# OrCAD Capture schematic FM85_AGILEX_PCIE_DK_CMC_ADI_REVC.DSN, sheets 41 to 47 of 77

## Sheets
41 FPGA Gnd 2: size B
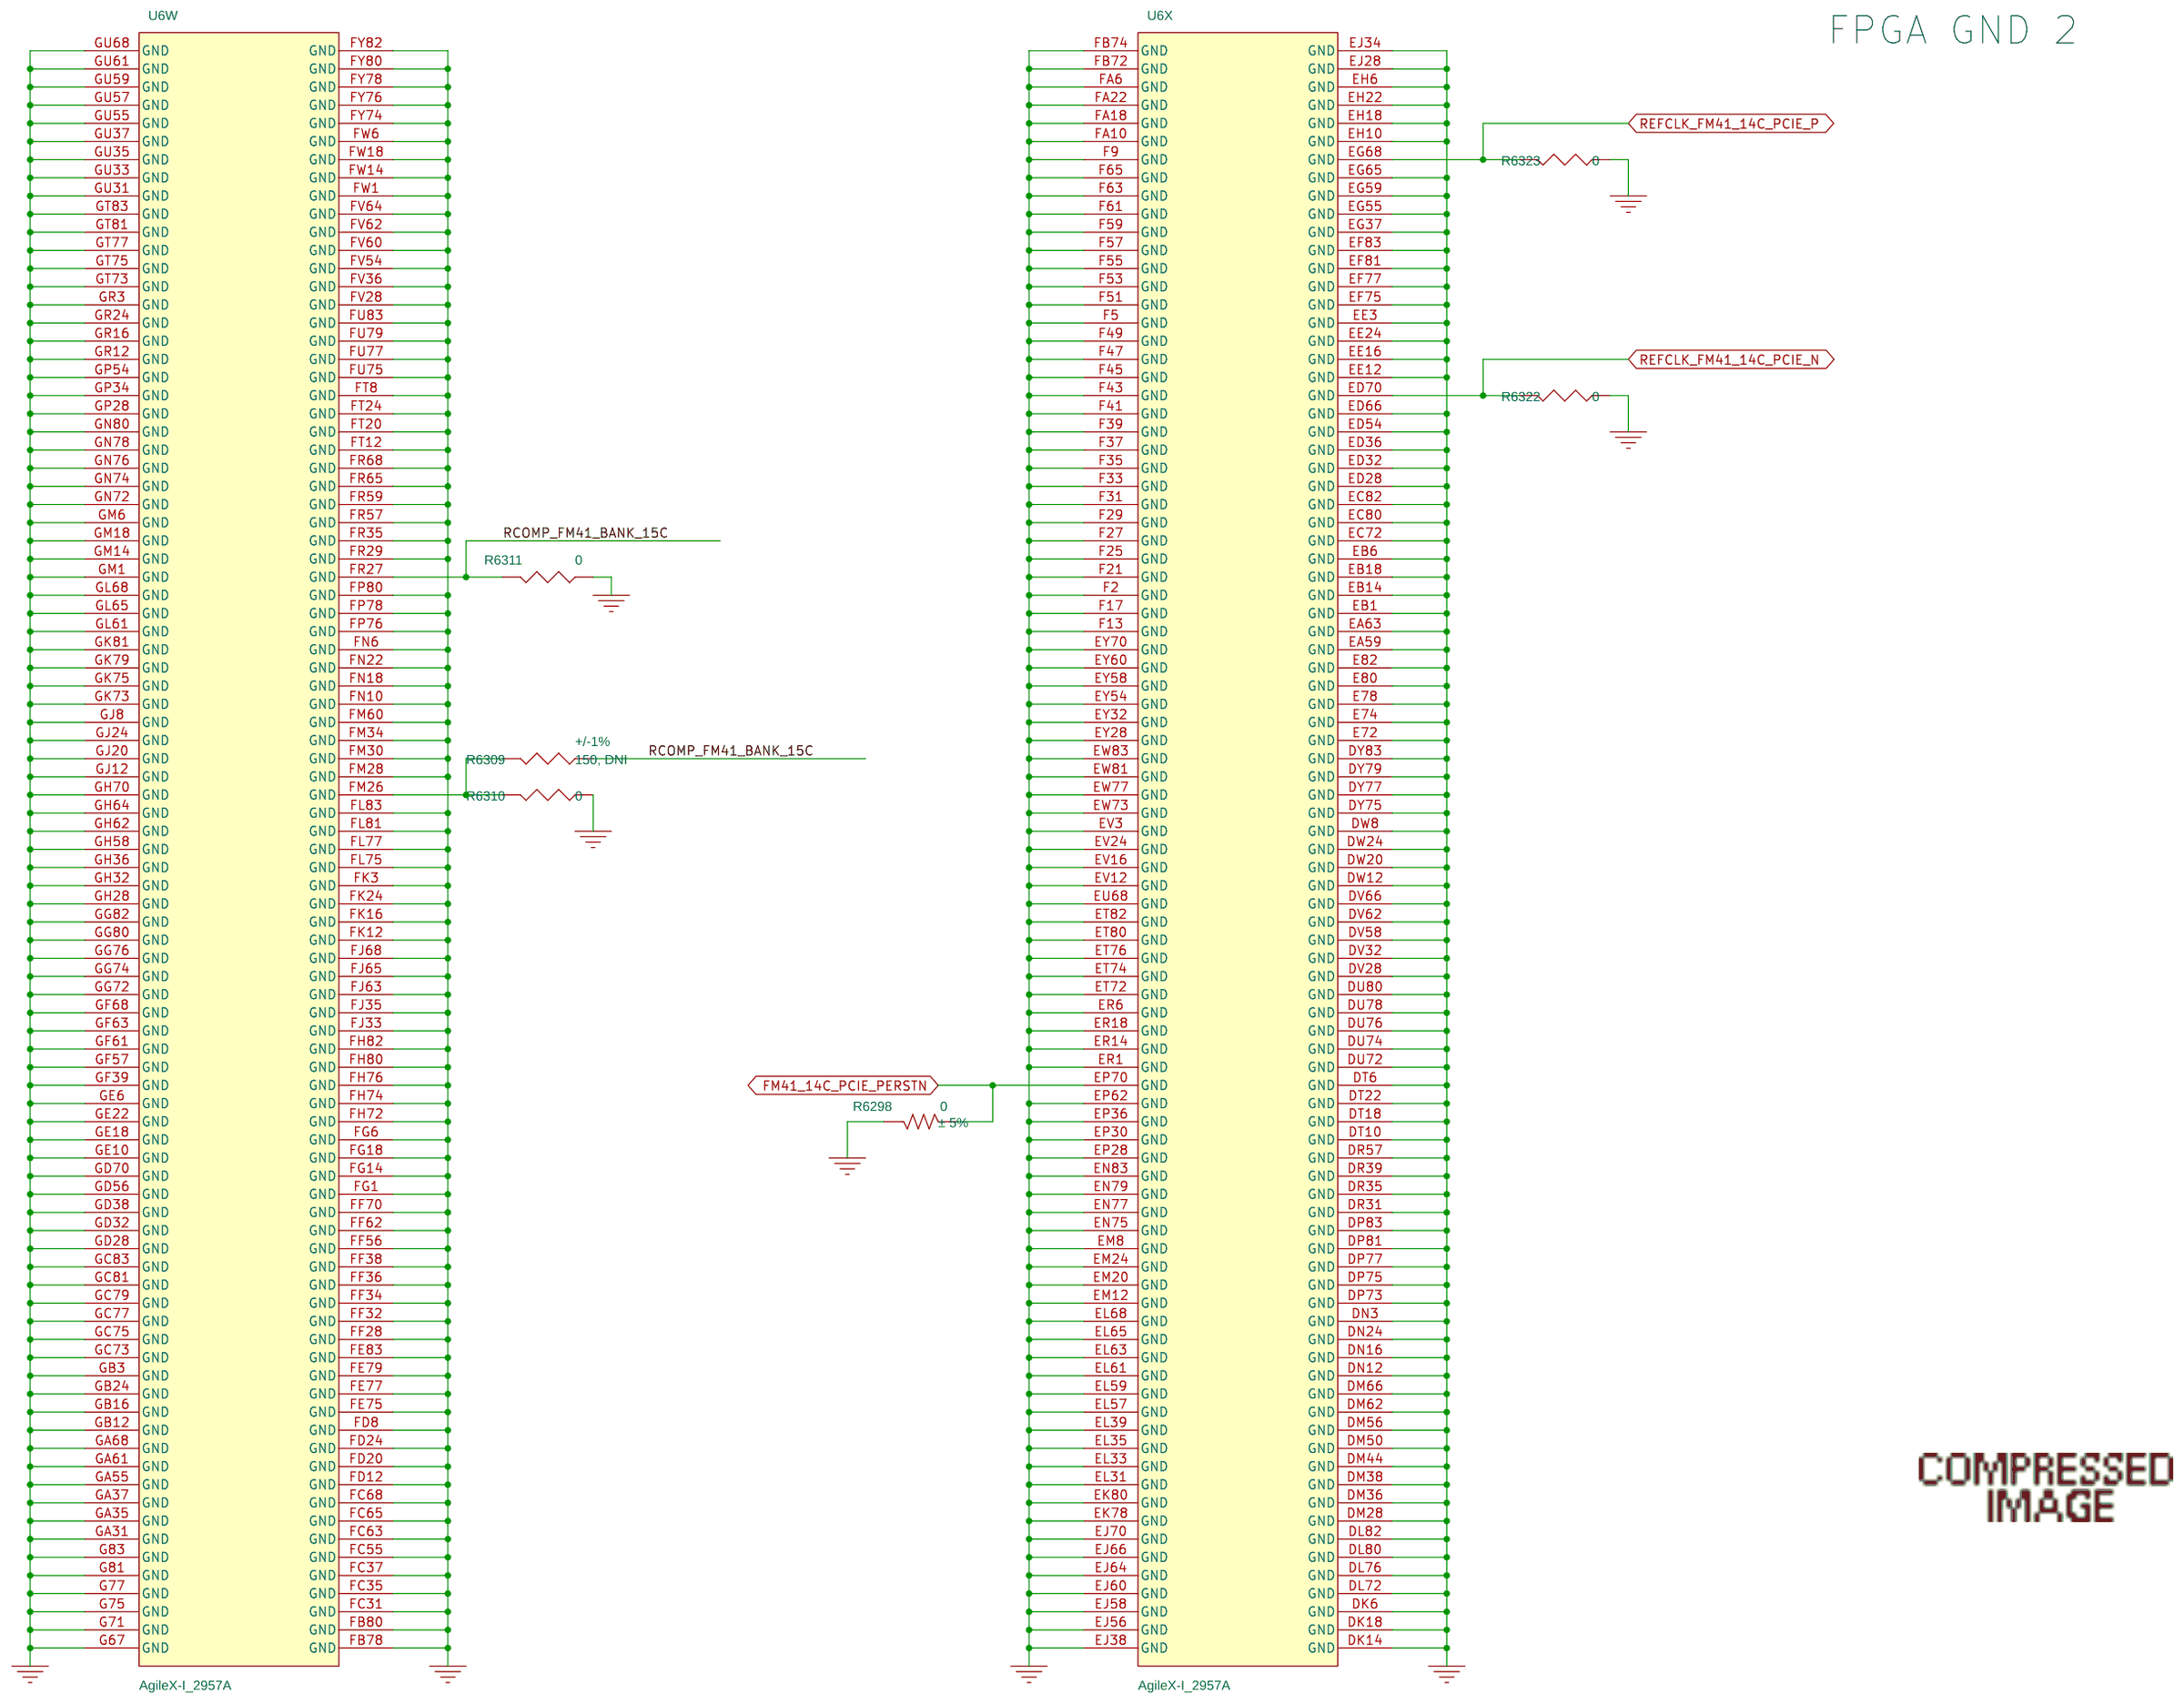
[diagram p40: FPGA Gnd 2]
42 FPGA Gnd 3: size B
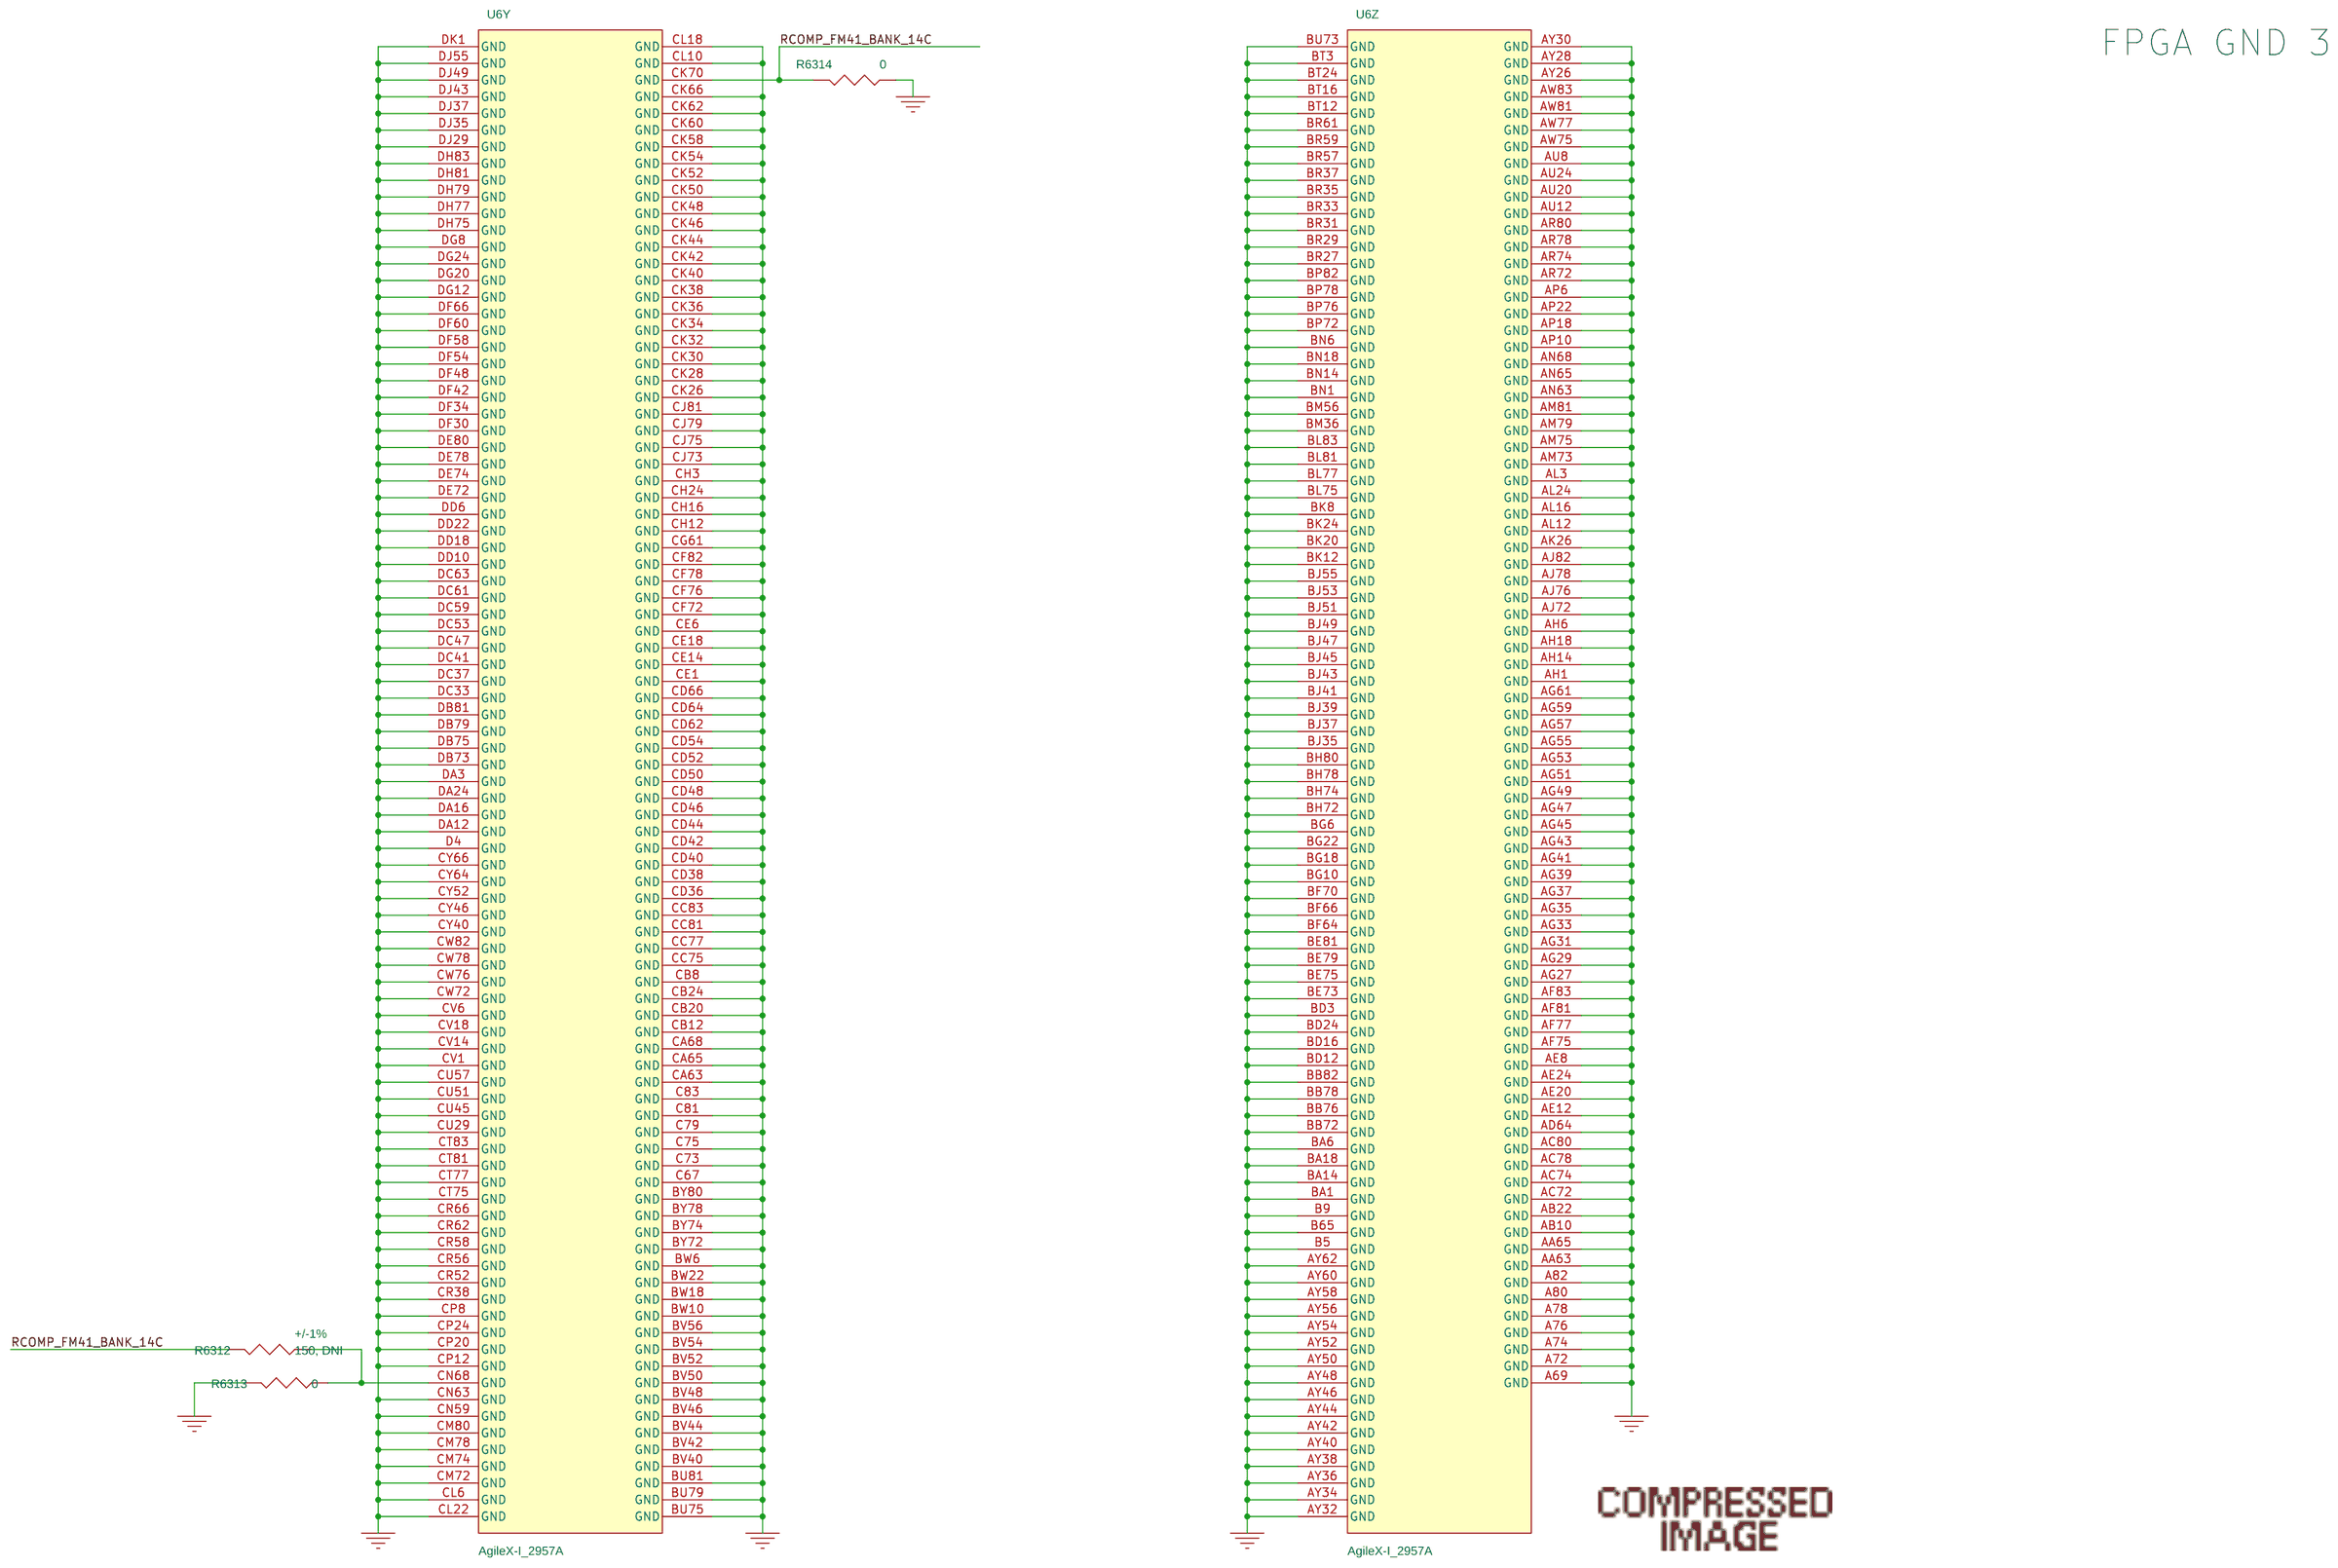
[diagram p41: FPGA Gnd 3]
43 Clock 1: size B
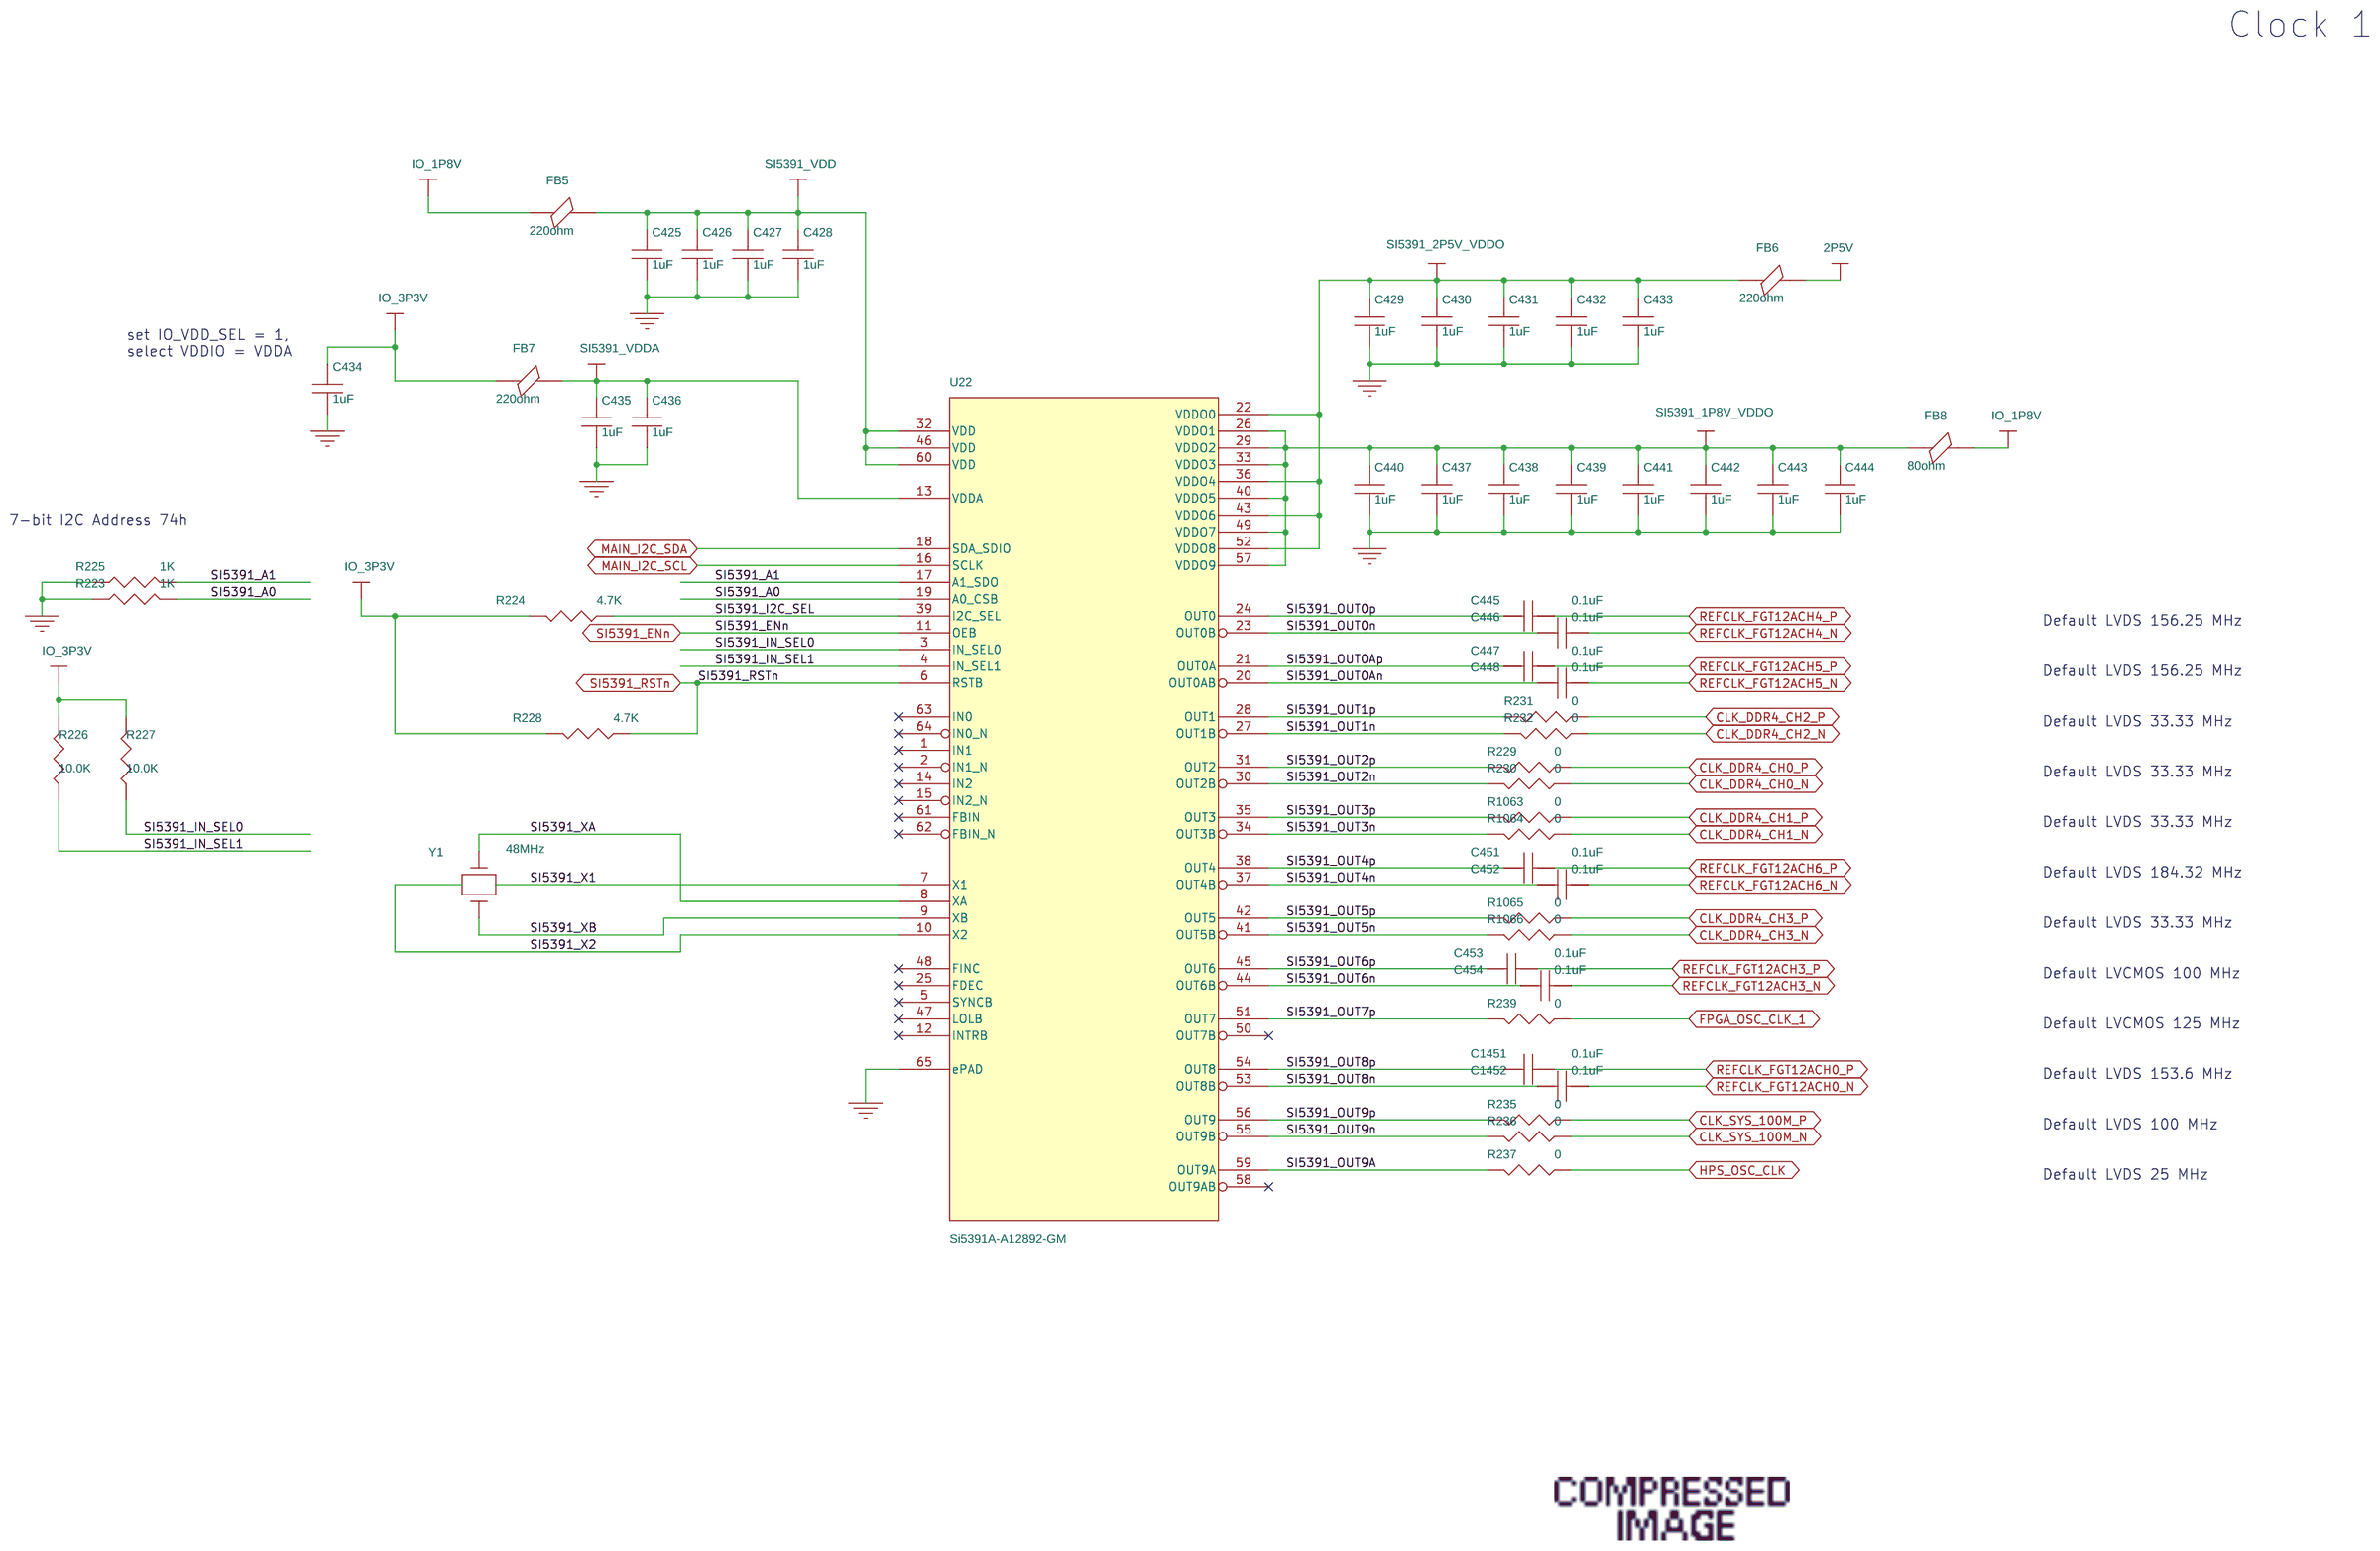
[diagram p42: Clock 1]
44 Clock 2: size B
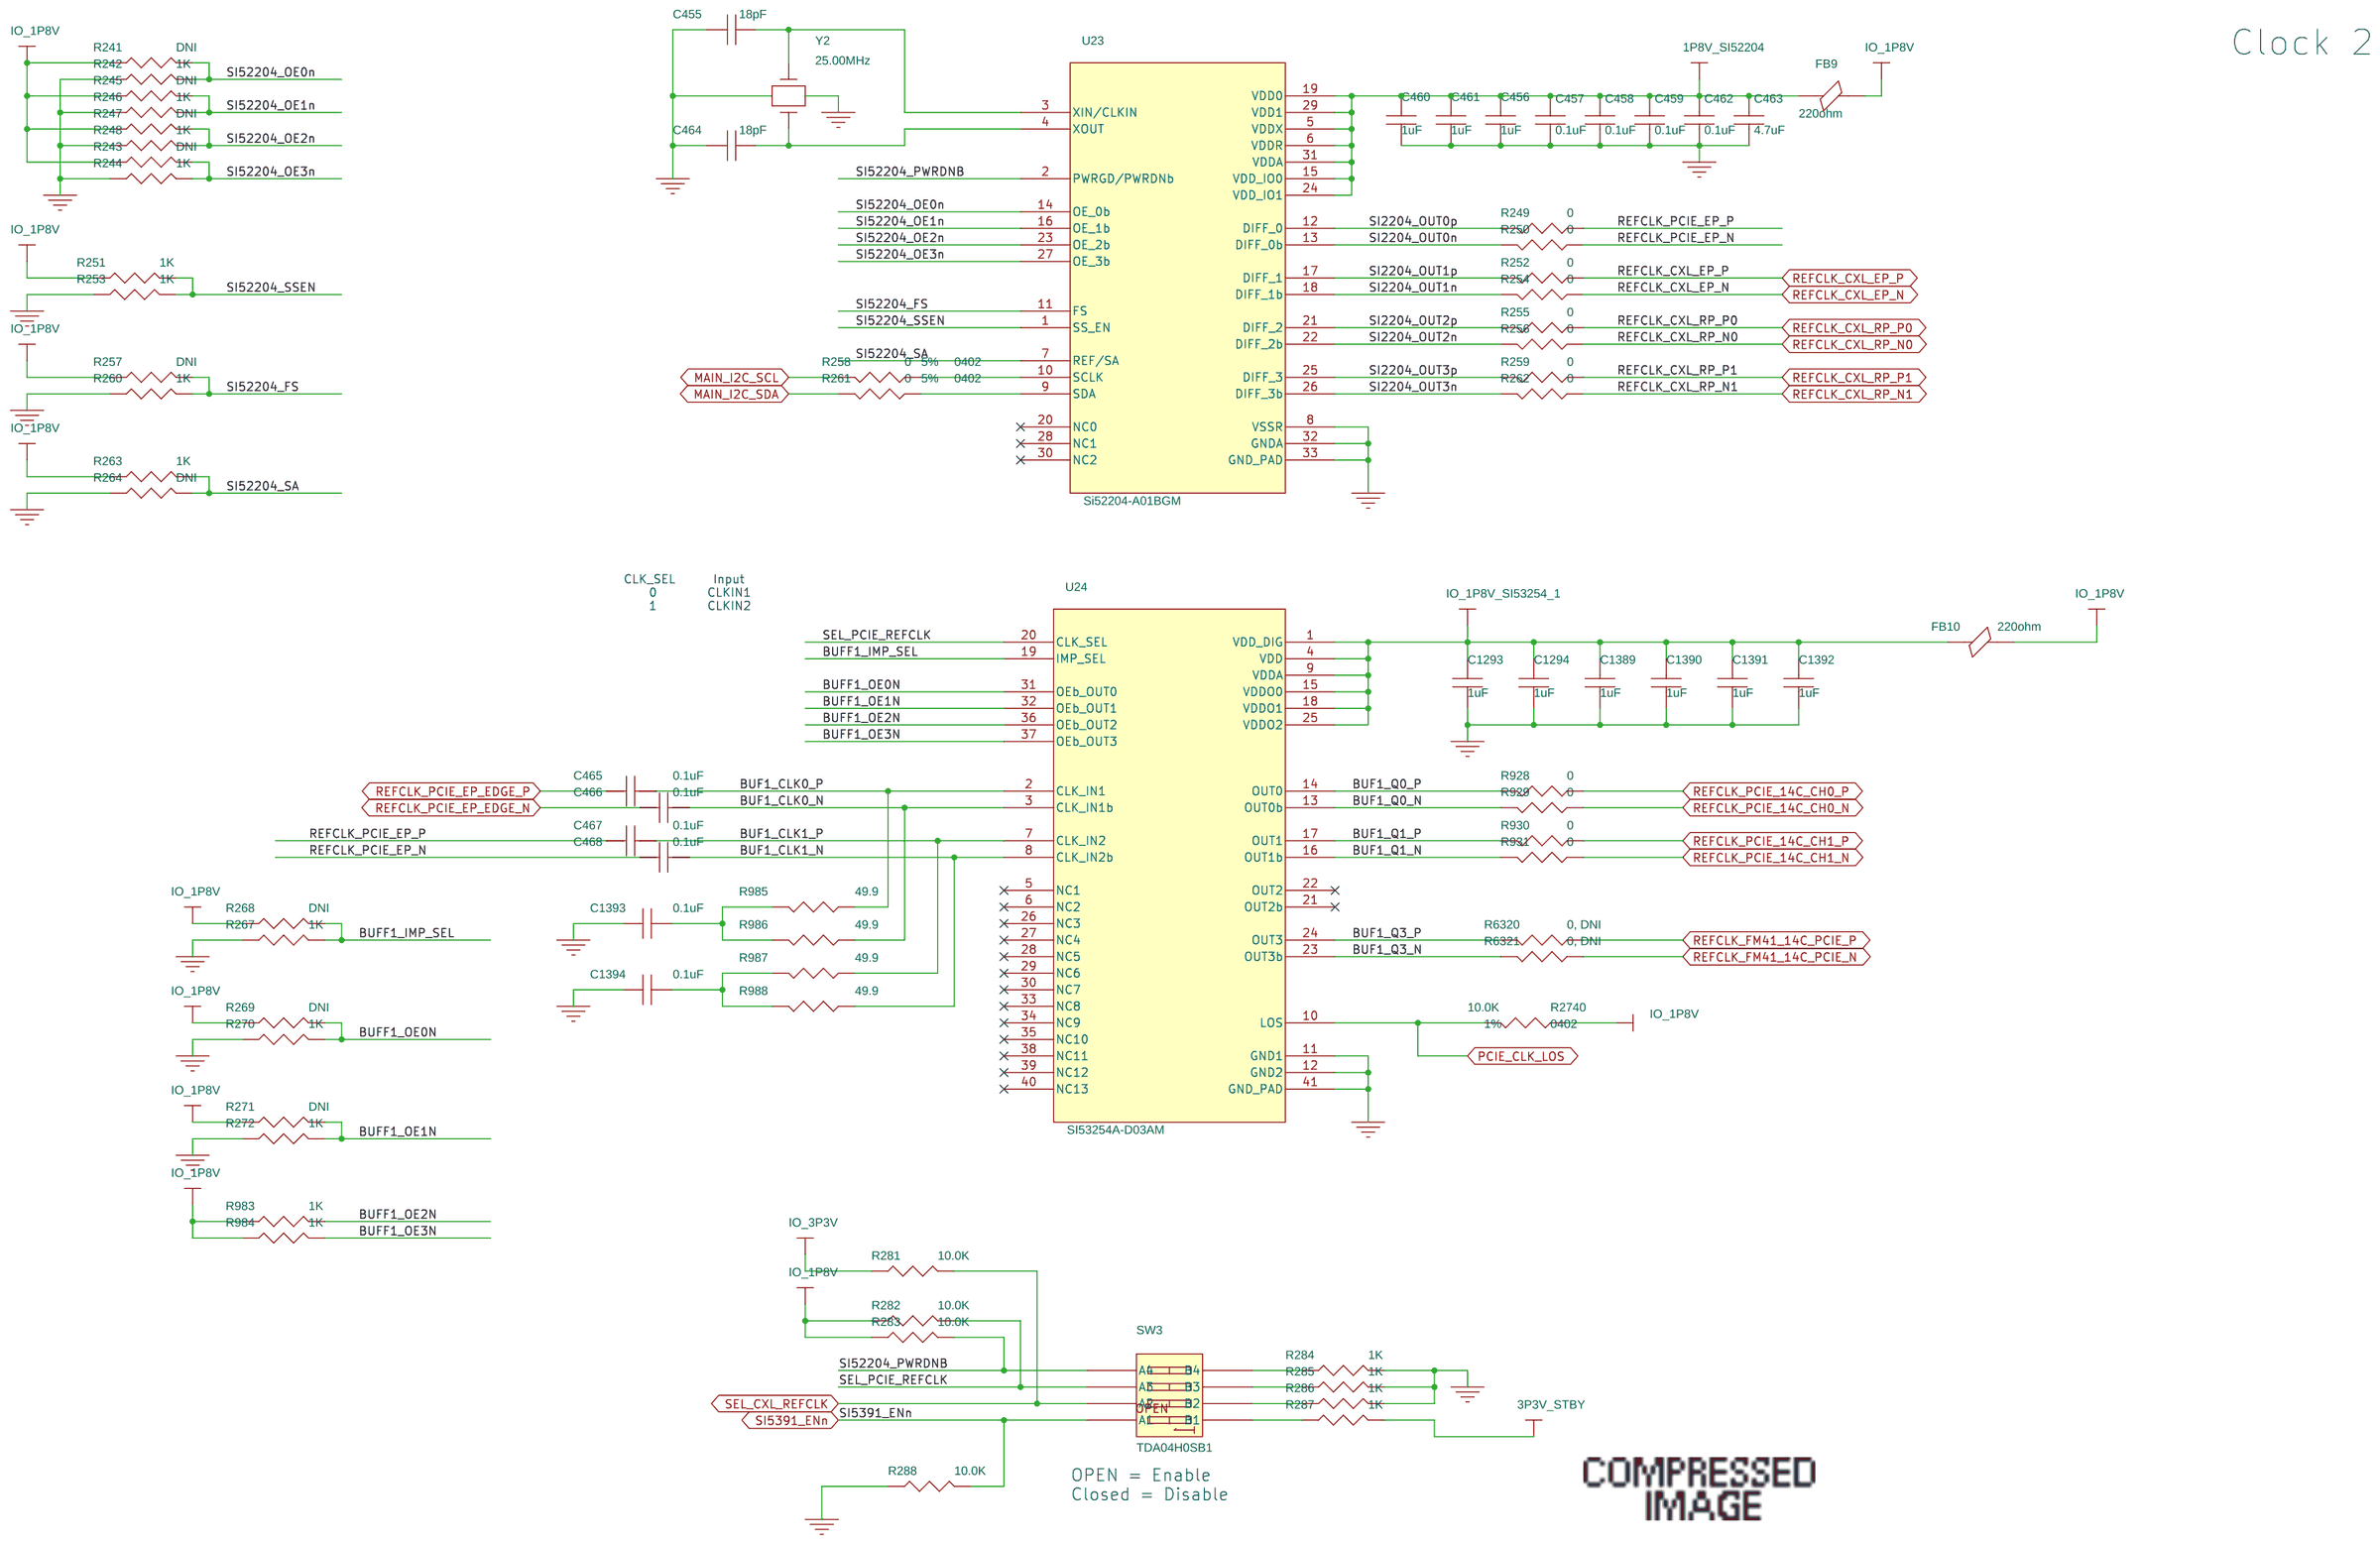
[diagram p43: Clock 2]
45 Clock 3: size B
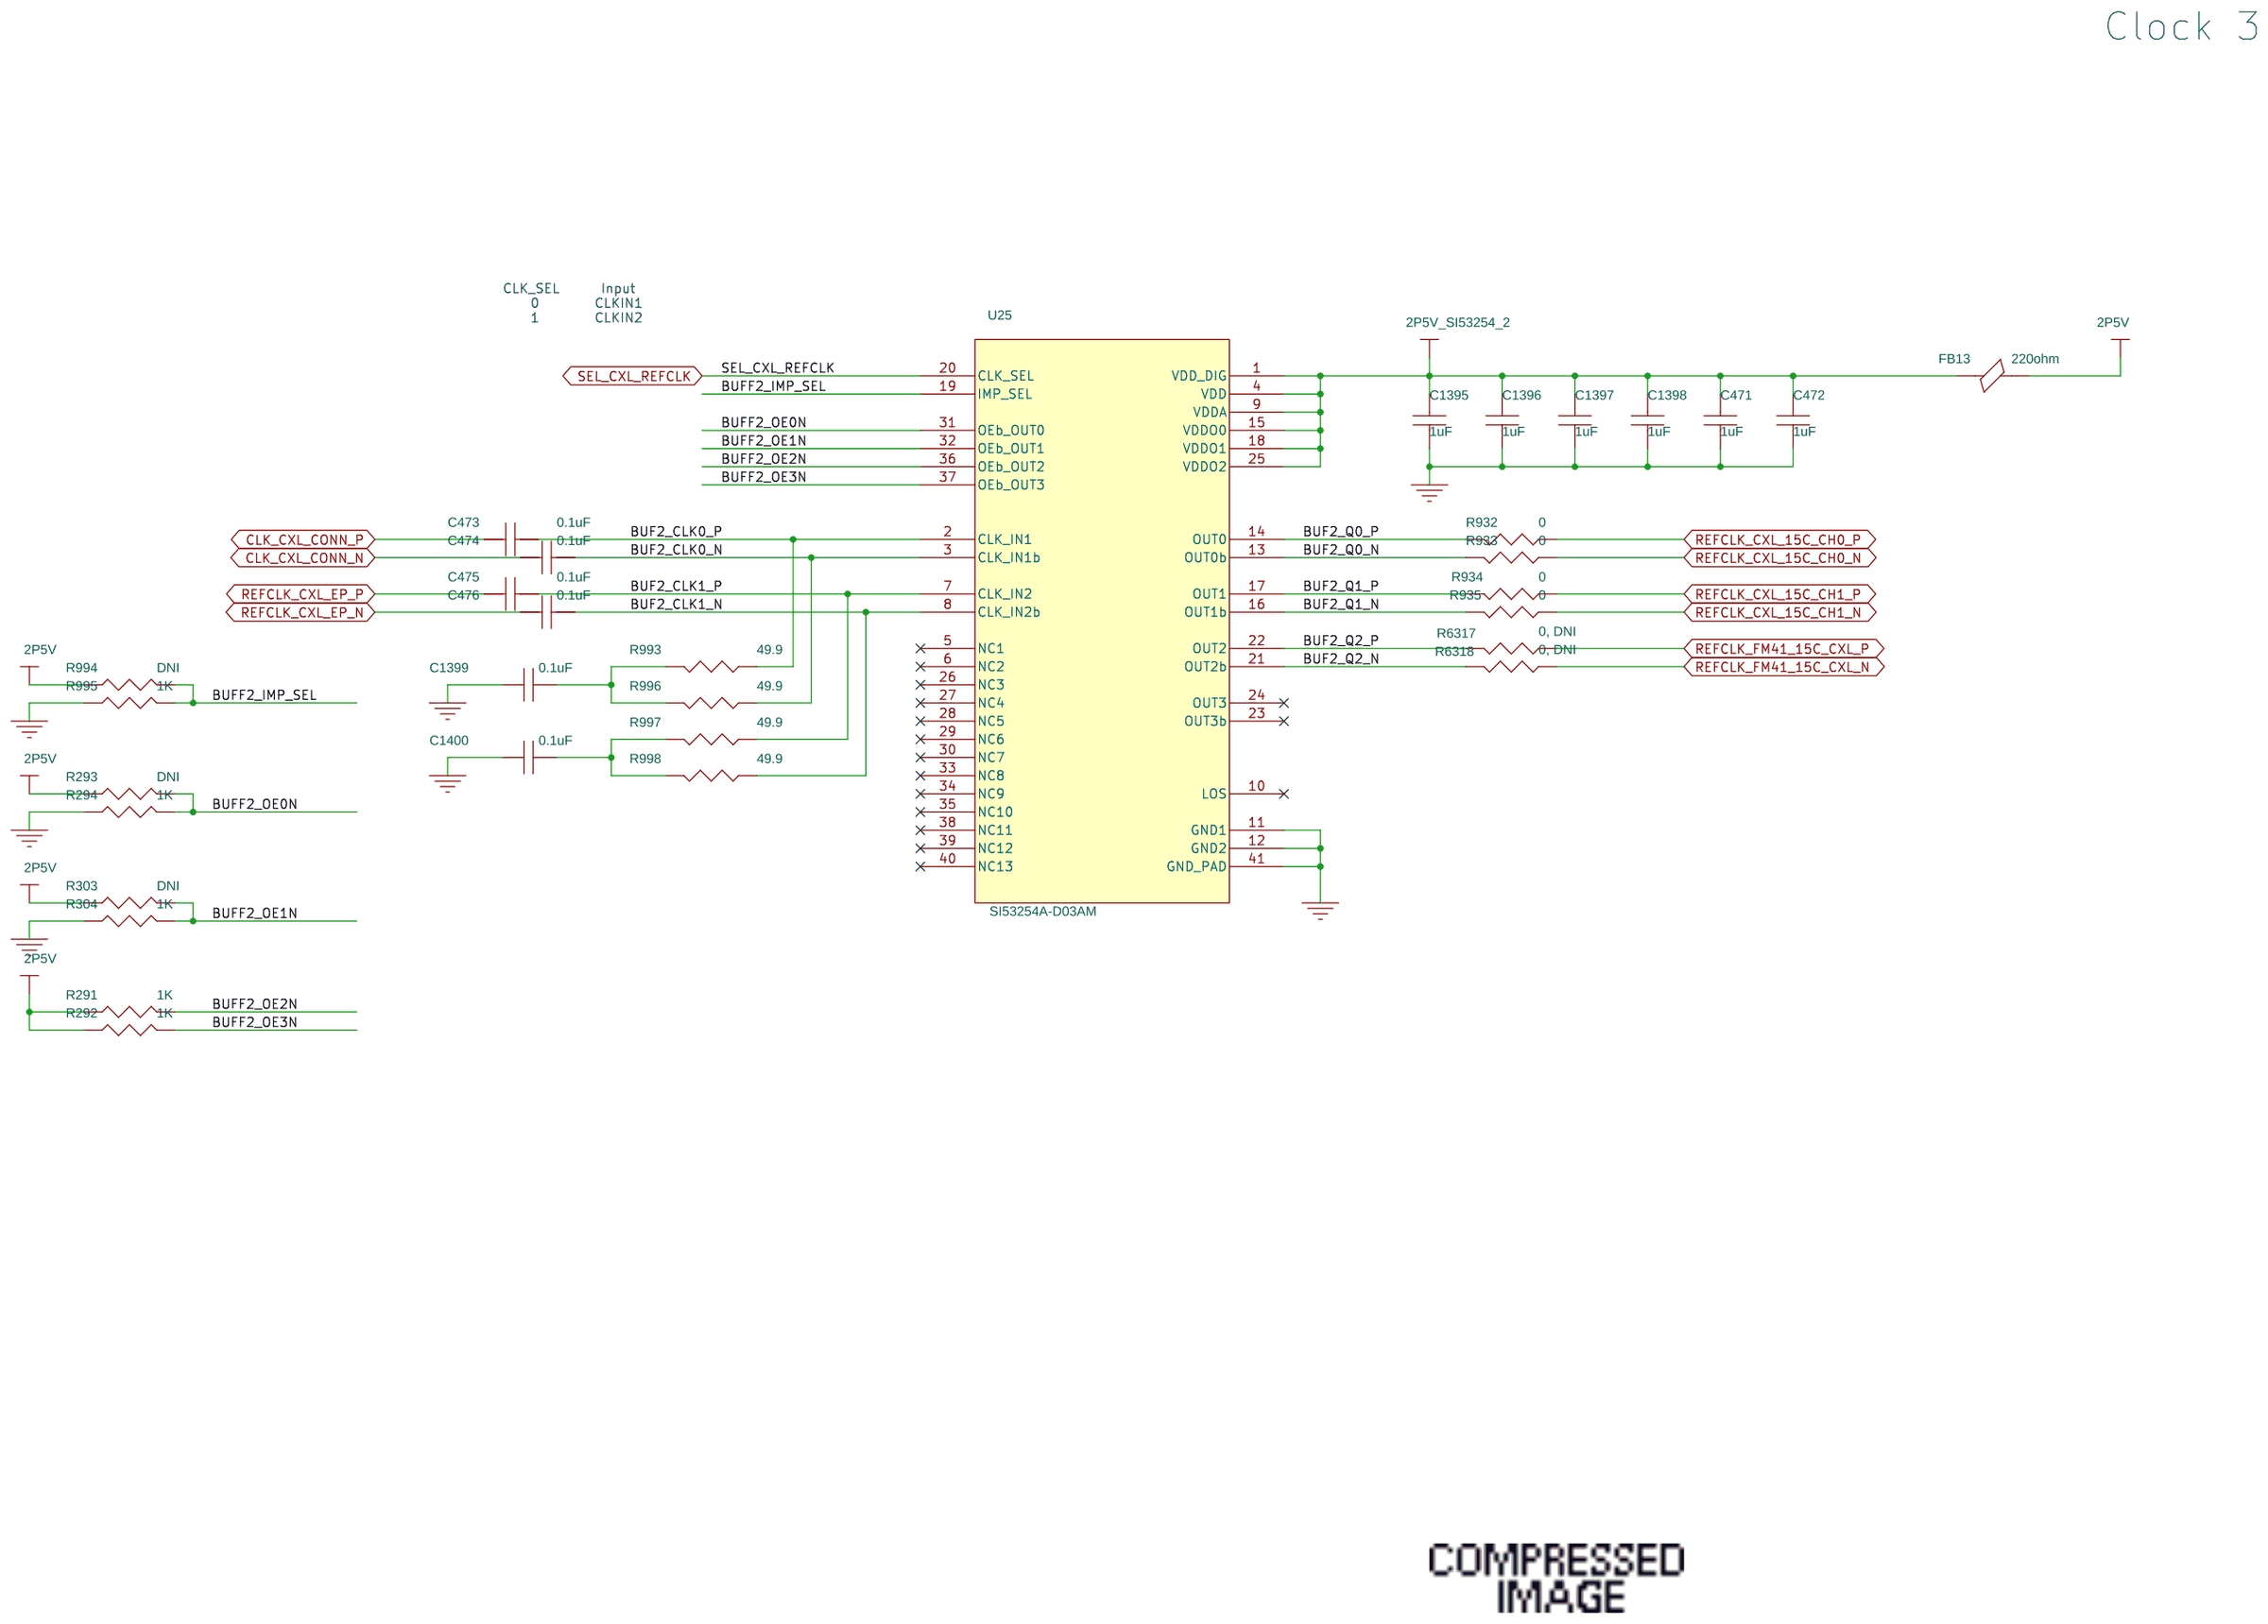
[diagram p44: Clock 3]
46 I2C And PMBUS: size B
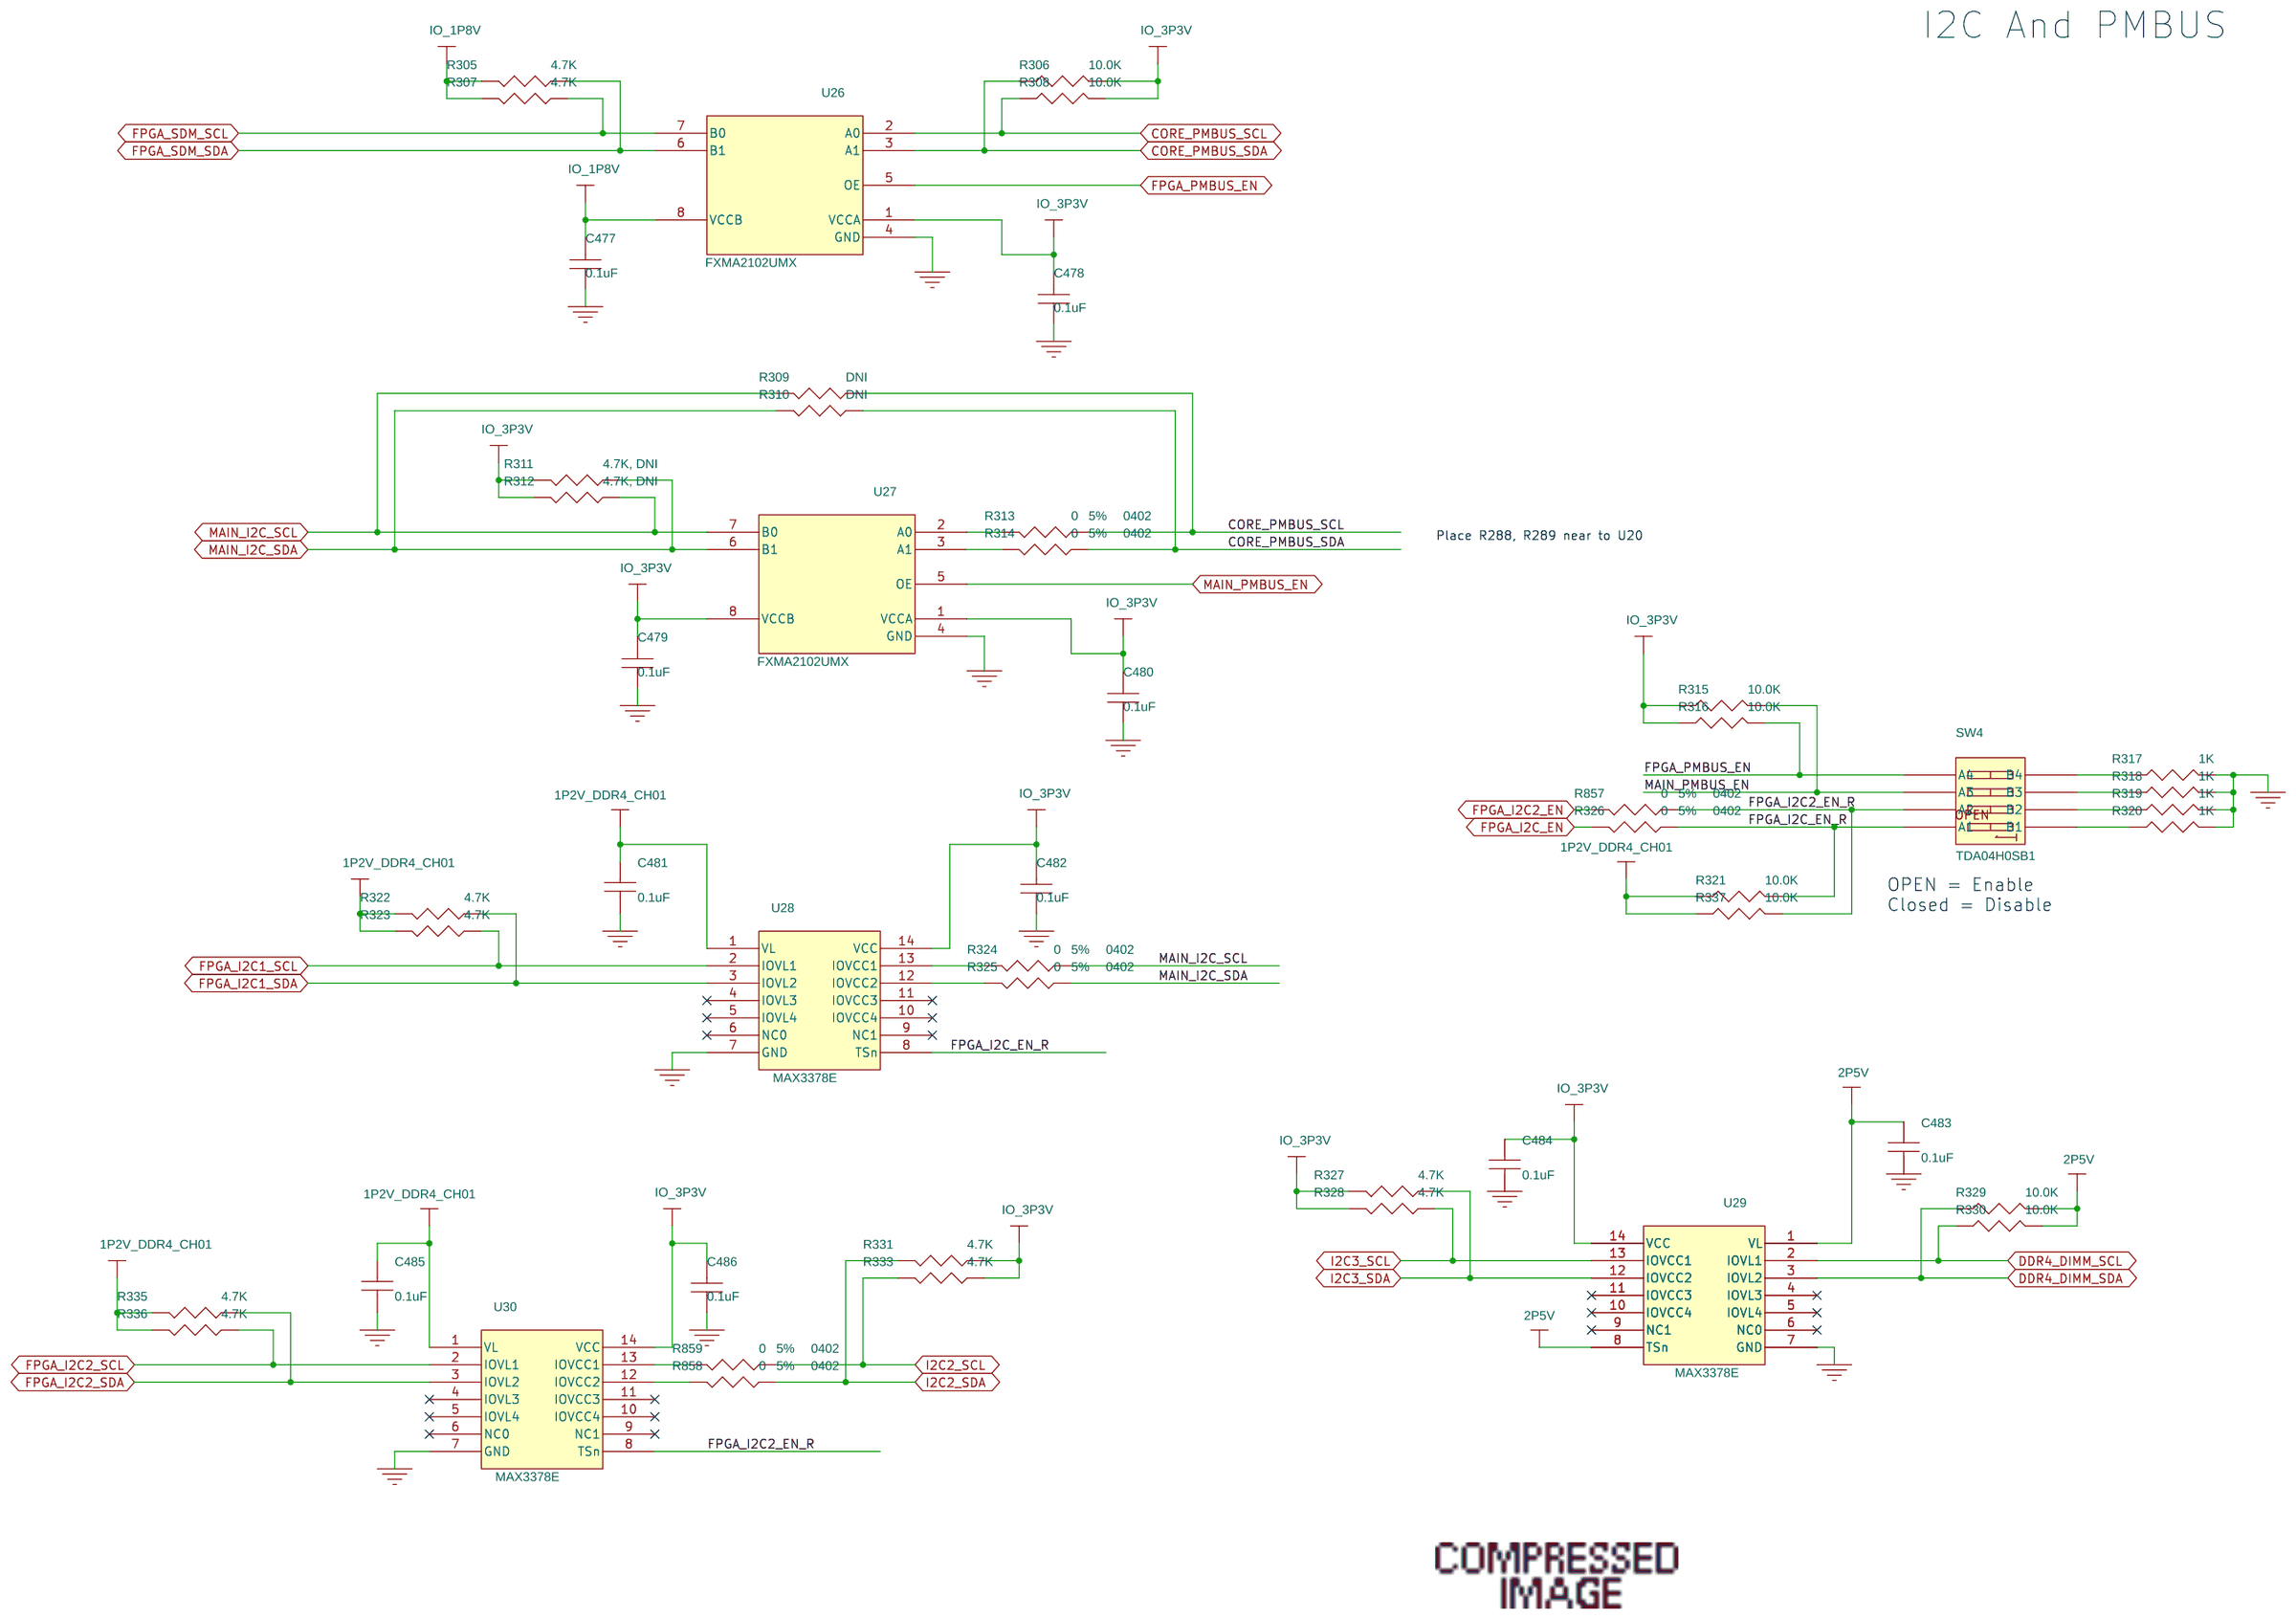
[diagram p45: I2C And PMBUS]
47 LEDs For QSFPDD: size B
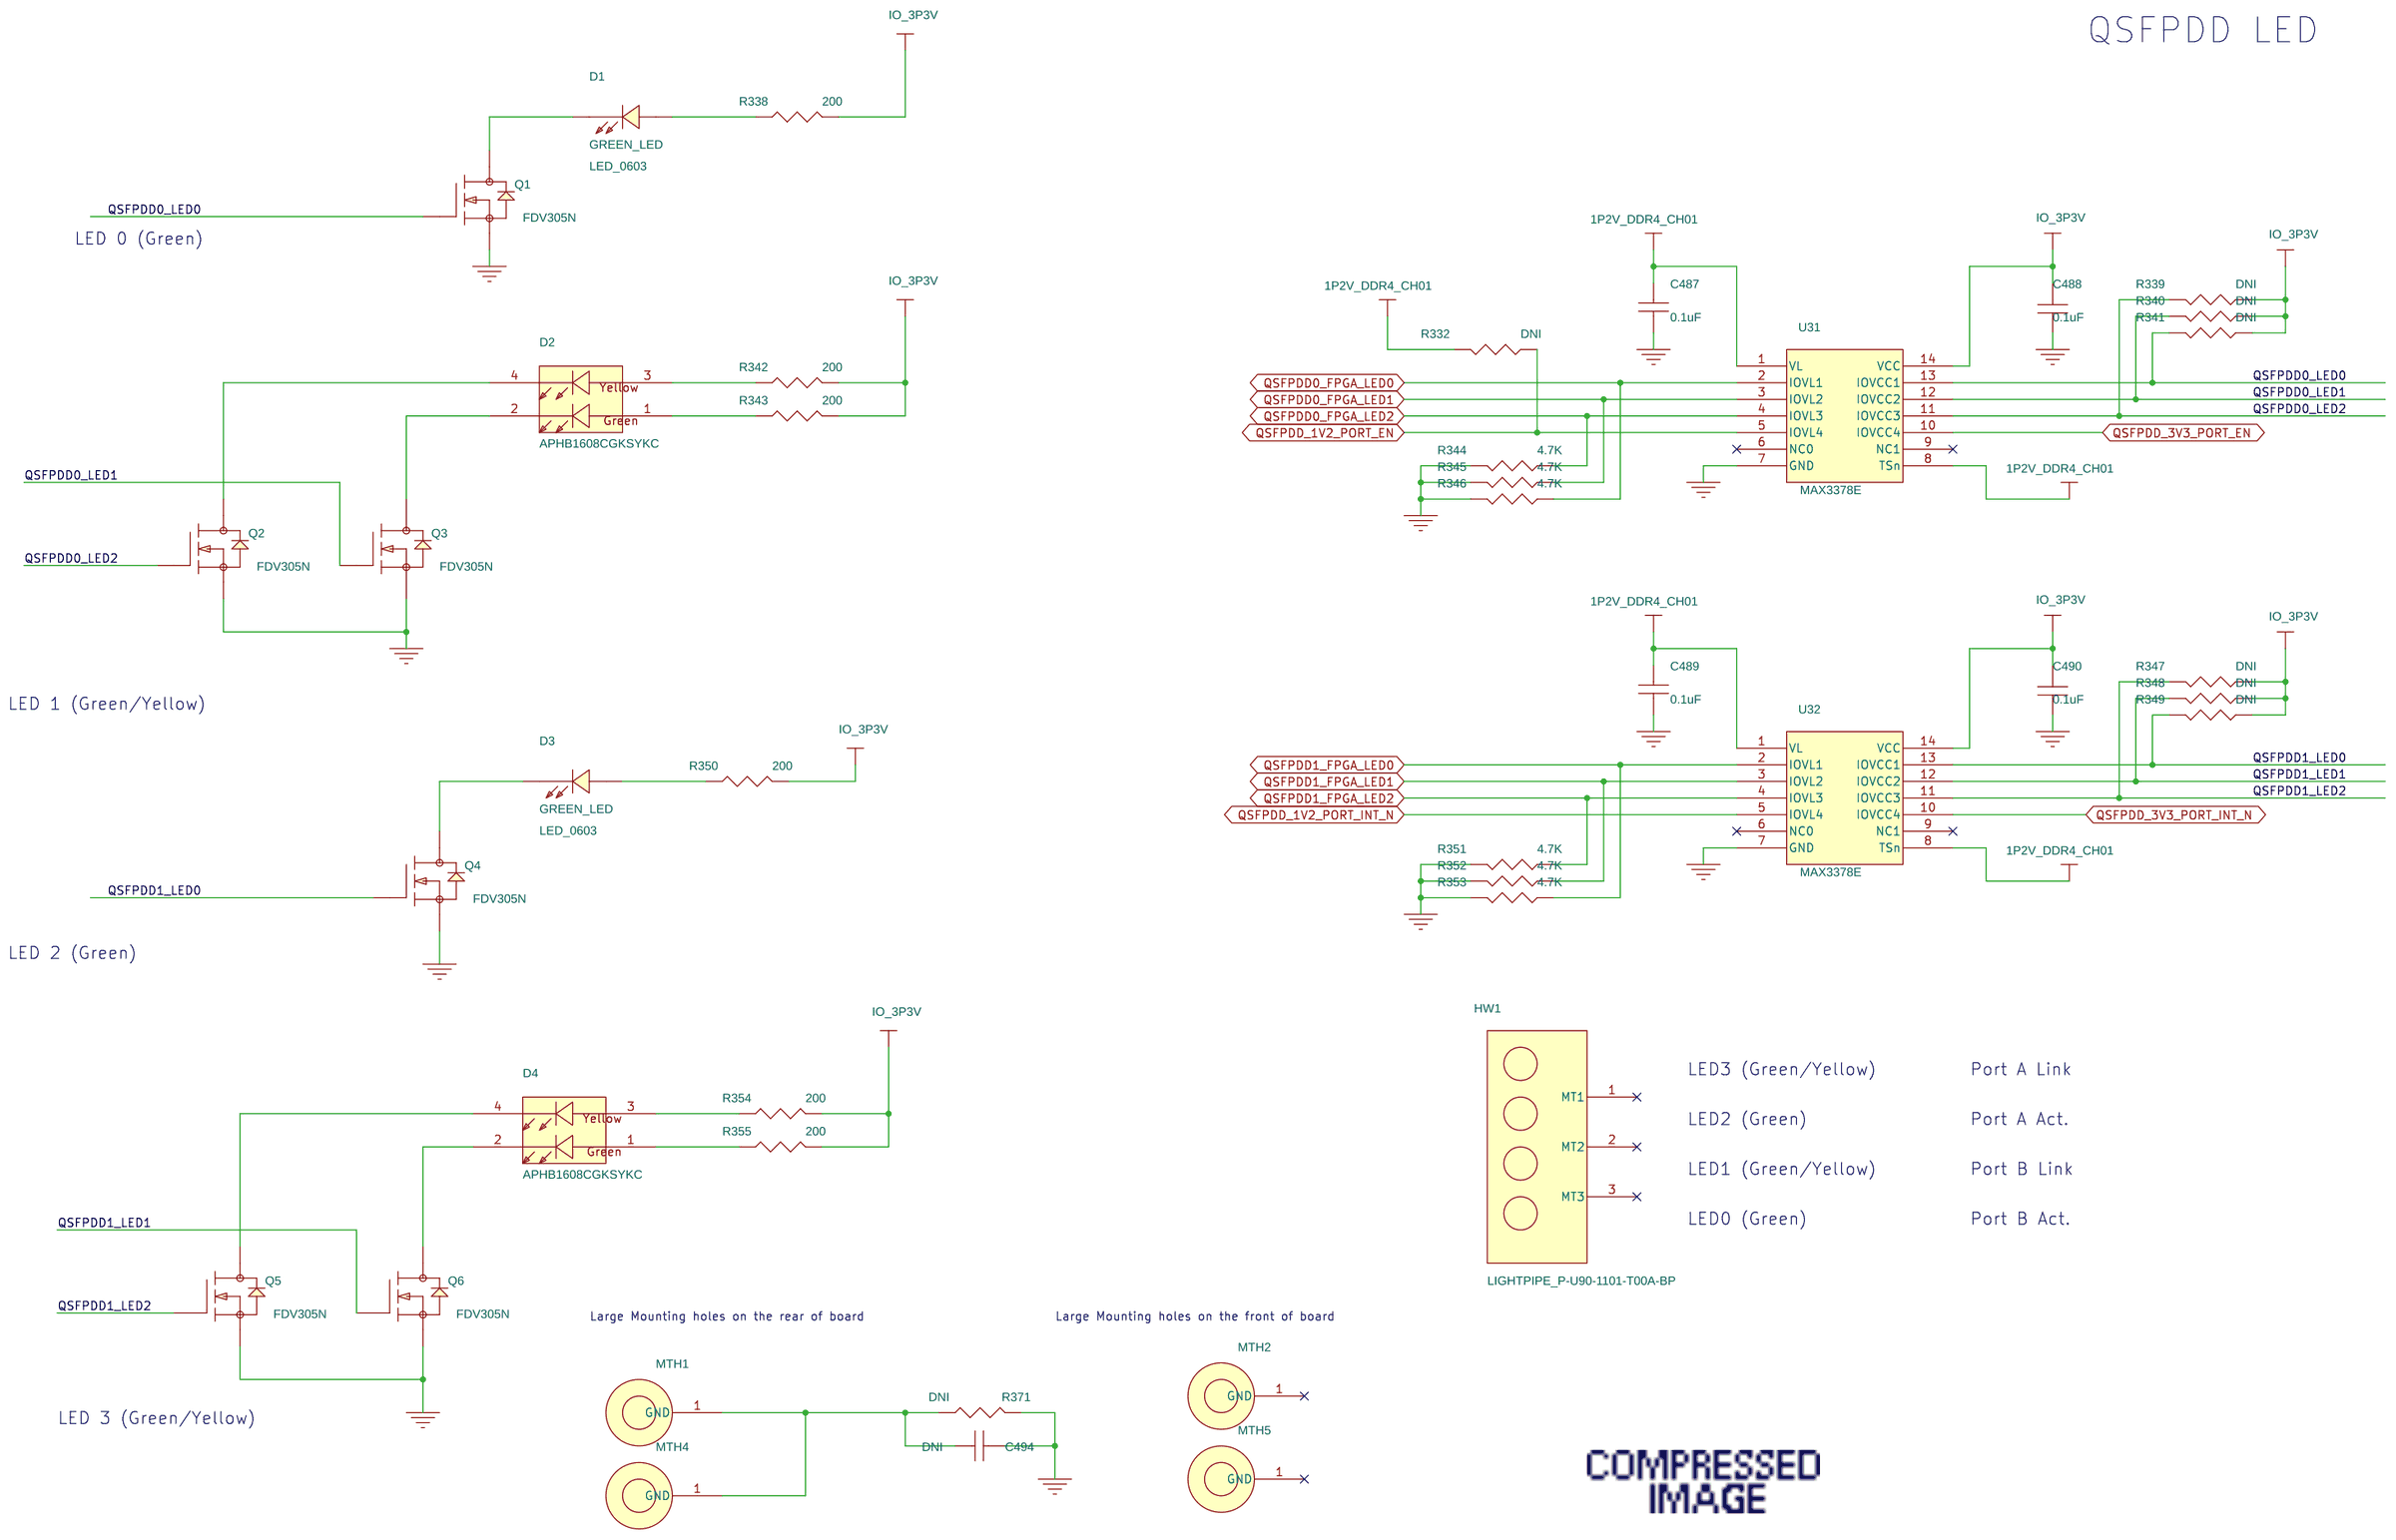
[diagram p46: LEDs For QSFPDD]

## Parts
sheet Clock 1
C425  1uF  [0402]
C426  1uF  [0402]
C427  1uF  [0402]
C428  1uF  [0402]
C429  1uF  [0402]
C430  1uF  [0402]
C431  1uF  [0402]
C432  1uF  [0402]
C433  1uF  [0402]
C434  1uF  [0402]
C435  1uF  [0402]
C436  1uF  [0402]
C437  1uF  [0402]
C438  1uF  [0402]
C439  1uF  [0402]
C440  1uF  [0402]
C441  1uF  [0402]
C442  1uF  [0402]
C443  1uF  [0402]
C444  1uF  [0402]
C445  0.1uF  [0402]
C446  0.1uF  [0402]
C447  0.1uF  [0402]
C448  0.1uF  [0402]
C451  0.1uF  [0402]
C452  0.1uF  [0402]
C453  0.1uF  [0402]
C454  0.1uF  [0402]
C1451  0.1uF  [0402]
C1452  0.1uF  [0402]
FB5  220ohm  [0402]
FB6  220ohm  [0402]
FB7  220ohm  [0402]
FB8  80ohm  [0805]
R223  1K  [0402]
R224  4.7K  [0402]
R225  1K  [0402]
R226  10.0K  [0402]
R227  10.0K  [0402]
R228  4.7K  [0402]
R229  0  [0402]
R230  0  [0402]
R231  0  [0402]
R232  0  [0402]
R235  0  [0402]
R236  0  [0402]
R237  0  [0402]
R239  0  [0402]
R1063  0  [0402]
R1064  0  [0402]
R1065  0  [0402]
R1066  0  [0402]
U22  Si5391A-A12892-GM  [QFN64_9x9_SI5391]
Y1  48MHz  [XTAL_3mmx2mm]
sheet Clock 2
C455  18pF  [0402]
C456  1uF  [0402]
C457  0.1uF  [0402]
C458  0.1uF  [0402]
C459  0.1uF  [0402]
C460  1uF  [0402]
C461  1uF  [0402]
C462  0.1uF  [0402]
C463  4.7uF  [0402]
C464  18pF  [0402]
C465  0.1uF  [0402]
C466  0.1uF  [0402]
C467  0.1uF  [0402]
C468  0.1uF  [0402]
C1293  1uF  [0402]
C1294  1uF  [0402]
C1389  1uF  [0402]
C1390  1uF  [0402]
C1391  1uF  [0402]
C1392  1uF  [0402]
C1393  0.1uF  [0402]
C1394  0.1uF  [0402]
FB9  220ohm  [0402]
FB10  220ohm  [0402]
R241  DNI  [0402]
R242  1K  [0402]
R243  DNI  [0402]
R244  1K  [0402]
R245  DNI  [0402]
R246  1K  [0402]
R247  DNI  [0402]
R248  1K  [0402]
R249  0  [0402]
R250  0  [0402]
R251  1K  [0402]
R252  0  [0402]
R253  1K  [0402]
R254  0  [0402]
R255  0  [0402]
R256  0  [0402]
R257  DNI  [0402]
R258  0  [0402]
R259  0  [0402]
R260  1K  [0402]
R261  0  [0402]
R262  0  [0402]
R263  1K  [0402]
R264  DNI  [0402]
R267  1K  [0402]
R268  DNI  [0402]
R269  DNI  [0402]
R270  1K  [0402]
R271  DNI  [0402]
R272  1K  [0402]
R281  10.0K  [0402]
R282  10.0K  [0402]
R283  10.0K  [0402]
R284  1K  [0402]
R285  1K  [0402]
R286  1K  [0402]
R287  1K  [0402]
R288  10.0K  [0402]
R928  0  [0402]
R929  0  [0402]
R930  0  [0402]
R931  0  [0402]
R983  1K  [0402]
R984  1K  [0402]
R985  49.9  [0402]
R986  49.9  [0402]
R987  49.9  [0402]
R988  49.9  [0402]
R2740  10.0K  [0402]
R6320  0, DNI  [0402]
R6321  0, DNI  [0402]
SW3  TDA04H0SB1  [DIPSWITCH_SMT_QUAD]
U23  Si52204-A01BGM  [QFN32L]
U24  SI53254A-D03AM  [SI53254_QFN40]
Y2  25.00MHz  [XTAL_FA-128]
sheet Clock 3
C471  1uF  [0402]
C472  1uF  [0402]
C473  0.1uF  [0402]
C474  0.1uF  [0402]
C475  0.1uF  [0402]
C476  0.1uF  [0402]
C1395  1uF  [0402]
C1396  1uF  [0402]
C1397  1uF  [0402]
C1398  1uF  [0402]
C1399  0.1uF  [0402]
C1400  0.1uF  [0402]
FB13  220ohm  [0402]
R291  1K  [0402]
R292  1K  [0402]
R293  DNI  [0402]
R294  1K  [0402]
R303  DNI  [0402]
R304  1K  [0402]
R932  0  [0402]
R933  0  [0402]
R934  0  [0402]
R935  0  [0402]
R993  49.9  [0402]
R994  DNI  [0402]
R995  1K  [0402]
R996  49.9  [0402]
R997  49.9  [0402]
R998  49.9  [0402]
R6317  0, DNI  [0402]
R6318  0, DNI  [0402]
U25  SI53254A-D03AM  [SI53254_QFN40]
sheet FPGA BANK 2F
U6  AgileX-I_2957A  [fbga2957a_hex_p56x45]  (sections A,B,C,D,E,F,G,H,I,J,K,L,M,N,O,P,Q,R,S,T,U,V,W,X,Y,Z)
sheet FPGA Gnd 2
R6298  0  [RESC1005X40L20L]
R6309  150, DNI  [0402]
R6310  0  [0402]
R6311  0  [0402]
R6322  0  [0402]
R6323  0  [0402]
sheet FPGA Gnd 3
R6312  150, DNI  [0402]
R6313  0  [0402]
R6314  0  [0402]
sheet I2C And PMBUS
C477  0.1uF  [0402]
C478  0.1uF  [0402]
C479  0.1uF  [0402]
C480  0.1uF  [0402]
C481  0.1uF  [0402]
C482  0.1uF  [0402]
C483  0.1uF  [0402]
C484  0.1uF  [0402]
C485  0.1uF  [0402]
C486  0.1uF  [0402]
R305  4.7K  [0402]
R306  10.0K  [0402]
R307  4.7K  [0402]
R308  10.0K  [0402]
R309  DNI  [0402]
R310  DNI  [0402]
R311  4.7K, DNI  [0402]
R312  4.7K, DNI  [0402]
R313  0  [0402]
R314  0  [0402]
R315  10.0K  [0402]
R316  10.0K  [0402]
R317  1K  [0402]
R318  1K  [0402]
R319  1K  [0402]
R320  1K  [0402]
R321  10.0K  [0402]
R322  4.7K  [0402]
R323  4.7K  [0402]
R324  0  [0402]
R325  0  [0402]
R326  0  [0402]
R327  4.7K  [0402]
R328  4.7K  [0402]
R329  10.0K  [0402]
R330  10.0K  [0402]
R331  4.7K  [0402]
R333  4.7K  [0402]
R335  4.7K  [0402]
R336  4.7K  [0402]
R337  10.0K  [0402]
R857  0  [0402]
R858  0  [0402]
R859  0  [0402]
SW4  TDA04H0SB1  [DIPSWITCH_SMT_QUAD]
U26  FXMA2102UMX  [UMLP]
U27  FXMA2102UMX  [UMLP]
U28  MAX3378E  [TSSOP-14]
U29  MAX3378E  [TSSOP-14]
U30  MAX3378E  [TSSOP-14]
sheet LEDs For QSFPDD
C487  0.1uF  [0402]
C488  0.1uF  [0402]
C489  0.1uF  [0402]
C490  0.1uF  [0402]
C494  DNI  [1206]
D1  GREEN_LED  [LED_0603]
D2  APHB1608CGKSYKC  [LED0603_4Pin_APHB1608]
D3  GREEN_LED  [LED_0603]
D4  APHB1608CGKSYKC  [LED0603_4Pin_APHB1608]
HW1  LIGHTPIPE_P-U90-1101-T00A-BP  [LIGHTPIPE_P-U90-1101-T00A-BP]
MTH1  MT_HOLE_GND  [MH_D125C175T_TB315]
MTH2  MT_HOLE_GND  [MH_D125C175T_TB315]
MTH4  MT_HOLE_GND  [MH_D125C175T_TB315]
MTH5  MT_HOLE_GND  [MH_D125C175T_TB315]
Q1  FDV305N  [SOT23]
Q2  FDV305N  [SOT23]
Q3  FDV305N  [SOT23]
Q4  FDV305N  [SOT23]
Q5  FDV305N  [SOT23]
Q6  FDV305N  [SOT23]
R332  DNI  [0402]
R338  200  [0402]
R339  DNI  [0402]
R340  DNI  [0402]
R341  DNI  [0402]
R342  200  [0402]
R343  200  [0402]
R344  4.7K  [0402]
R345  4.7K  [0402]
R346  4.7K  [0402]
R347  DNI  [0402]
R348  DNI  [0402]
R349  DNI  [0402]
R350  200  [0402]
R351  4.7K  [0402]
R352  4.7K  [0402]
R353  4.7K  [0402]
R354  200  [0402]
R355  200  [0402]
R371  DNI  [0402]
U31  MAX3378E  [TSSOP-14]
U32  MAX3378E  [TSSOP-14]

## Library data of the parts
C425-C444 = CAP: CAP - CER, 1uF, 10V, +/-10%, X5R, 0402; Item Num: G61001-001; Lead Free Status: Yes; Manufacturer: Murata; Manufacturer Part Num: GRM155R61A105KE15D; Num Pins: 2; Part Class: CAPACITORS; RoHS Compliant: Yes
C445-C448 C451-C454 C465-C468 C473-C476 C1393 C1394 C1399 C1400 C1451 C1452 = CAP: CAPC,  X7R, 0402, 0.1uF, 25V, ±20%; Dielectric: X5R; Item Num: K13660-001; LIFECYCLE_PHASE: Active; Lead Free Status: Lead Free; Manufacturer: Murata; Manufacturer Part Num: GRM155R71E104KE14D; Num Pins: 2; Part Class: CAPACITORS; Price: 0.07; RoHS Compliant: RoHS Compliant; Tolerance: +80%/-20%
FB5-FB7 = BEAD_FERRITE_SM: FER-BEAD,0402,220.0OHM,580.0MA,+/-25%; Imax (A): 600mA; Item Num: A51464-023; Manufacturer: Murata Electronics; Manufacturer Part Num: BLM15AX221SN1D; Rdc (Ohms): 350mOhm; Tolerance (%): 25%
FB8 = BEAD_FERRITE_SM: FERRITE,CHIP,POWER,80OHM,SMD; Imax (A): 300mA; Item Num: G32678-001; Manufacturer: Laird-Signal Integrity Products; Manufacturer Part Num: HI0805R800R-10; Rdc (Ohms): 350mOhm; Tolerance (%): 25%
R223 R225 R241-R248 R251 R253 R257 R260 R263 R264 R267-R272 R284-R287 R291-R294 R303 R304 R317-R320 R983 R984 R994 R995 = RESISTOR: RES,1.00K OHMS,1.0%,1/16W,0402; Item Num: G60609-021; Lead Free Status: No; Manufacturer: Panasonic; Manufacturer Part Num: ERJ-2RKF1001X; Num Pins: 2; Part Class: Resistors
R224 R228 R305 R307 R311 R312 R322 R323 R327 R328 R331-R333 R335 R336 R339-R341 R344-R349 R351-R353 = RESISTOR: RES 4.7K OHM 1/16W 5% 0402 SMD; Item Num: A93549-020; Lead Free Status: No; Manufacturer: Panasonic; Manufacturer Part Num: ERJ-2GEJ472X; Manufacturer's Part No.: ERJ-2GEJ472X; Num Pins: 2; Part Class: RESISTORS; Price: 0; RoHS Compliant: Yes
R226 R227 R281-R283 R288 R306 R308 R315 R316 R321 R329 R330 R337 = RESISTOR: RES,10.0K OHMS,1.0%,1/16W, 0402; AGILE_LINK: http://sj-agile9app/Agile/PLMServlet?action=OpenEmailObject&classid=10000&objid=146548997; Item Num: K28115-001; LIFECYCLE_PHASE: Active; Lead Free Status: No; MFR_LIFECYCLE: Active; Manufacturer: Panasonic; Manufacturer Part Num: ERJ-2RKF1002X; Num Pins: 2; PART_SUBCLASS: RESISTORS; POWER: 1/16W; RoHS Compliant: Yes; TOLERANCE: +/-1%
R229-R232 R235-R237 R239 R249 R250 R252 R254-R256 R259 R262 R928-R935 R1063-R1066 = RES_0_OHM_5%_1_16W_0402_SMD: Item Num: H30887-001
U22 = Si5341A-A-GM_0: SILABS 5391A CLK CHIP FM85,FPGA DK U22 (PRE-PROG)ADDR 74H; Item Num: M27305-001; Manufacturer: Silicon Laboratories; Manufacturer Part Num: SI5391A-A12892-GM
Y1 = CRYSTAL_SM_13: CRYSTAL - 48MHz +/-10ppm 8pF 23OHM -40°C ~ 85°C AEC-Q200 4-SMD DFN; Item Num: K15539-001; Lead Free Status: Yes; MFR_LIFECYCLE: Active; Manufacturer: AVX Corp/Kyocera Corp; Manufacturer Part Num: CX3225SB48000D0FPJC1; Num Pins: 4; RoHS Compliant: Yes
C455 C464 = CAP: CAP - CERAMIC, 18PF, 5%, 50V, 0402, COG; AGILE_LINK: http://sj-agile9app/Agile/PLMServlet?action=OpenEmailObject&classid=10000&objid=213459014; Item Num: E60713-001; Lead Free Status: Lead Free; MFR_LIFECYCLE: Active; Manufacturer: Murata; Manufacturer Part Num: GRM1555C1H180JZ01D; Num Pins: 2; PART_SUBCLASS: CAPACITORS; RoHS Compliant: Yes
C456 C460 C461 C471 C472 C1293 C1294 C1389-C1392 C1395-C1398 = CAP: CAP - CER, 1uF, 10V, +/-10%, X5R, 0402; Item Num: G61001-001; Lead Free Status: No; Manufacturer: Murata; Manufacturer Part Num: GRM155R61A105KE15D; Num Pins: 2; Part Class: Capacitors; Price: 0; RoHS Compliant: Yes
C457-C459 C462 = CAP: CAPC,  X7R, 0402, 0.1uF, 25V, ±20%; AGILE_LINK: http://sj-agile9app/Agile/PLMServlet?action=OpenEmailObject&classid=10000&objid=213459527; Item Num: K13660-001; LIFECYCLE_PHASE: Active; Lead Free Status: Lead Free; MFR_LIFECYCLE: Active; Manufacturer: Murata; Manufacturer Part Num: GRM155R71E104KE14D; Num Pins: 2; PART_SUBCLASS: CAPACITORS; Part Class: CAPACITORS; RATED_VOLTAGE: 25V; RoHS Compliant: RoHS Compliant; TOLERANCE: +80%/-20%
C463 = CAP: CAP - CER 4.7UF, +/-20%, 6.3V, X5R, 0402; Item Num: A36096-107; Manufacturer: Murata; Manufacturer Part Num: GRM155R60J475ME87D; Tolerance: +/-20%; Voltage: 6.3V
FB9 FB10 FB13 = BEAD_FERRITE_SM: IND - SMD EMI FILTERS/CHIP FERRITE BEAD, 220-OHM @ 100MHZ, 0.35-OHM DCR, 0402; Imax (A): 300mA; Item Num: G79186-002; Manufacturer: Wurth Elektronik; Manufacturer Part Num: 742792780; Rdc (Ohms): 350mOhm; Tolerance (%): 25%
R258 R261 R313 R314 R324-R326 R857-R859 = RESISTOR: RES ZERO OHM 1/16W 5% 0402 SMD; Altera Part No.: P02-14020R; Item Num: H30887-001; Lead Free Status: No; Manufacturer: Panasonic; Manufacturer Part Num: ERJ-2GE0R00X; Num Pins: 2; Part Class: RESISTORS; RoHS Compliant: Yes; Tolerance: 5%
R985-R988 R993 R996-R998 = RESISTOR: RES, 49.9 OHMS, 1%, 1/16W, 0402; Item Num: K16545-001; Lead Free Status: Yes; Manufacturer: NIC Components Corp.; Manufacturer Part Num: NRC04F49R9TRF; Num Pins: 2; Part Class: Resistors; Price: 0
R2740 = RESISTOR: RES,10.0K OHMS,1.0%,1/16W, 0402; AGILE_LINK: http://sj-agile9app/Agile/PLMServlet?action=OpenEmailObject&classid=10000&objid=146548997; Item Num: K28115-001; LIFECYCLE_PHASE: Active; Lead Free Status: No; MFR_LIFECYCLE: Active; Manufacturer: Panasonic; Manufacturer Part Num: ERJ-2RKF1002X; Num Pins: 2; PART_SUBCLASS: RESISTORS; POWER: 1/16W; RESISTANCE: 10K; RoHS Compliant: Yes; TOLERANCE: 1%
R6317 R6318 R6320 R6321 = RESISTOR: RES ZERO OHM 1/16W 5% 0402 SMD; Agile IPN: P02-14020R; Altera Part No.: P02-14020R; Item Num: H30887-001; Lead Free Status: No; Manufacturer: Panasonic; Manufacturer Part Num: ERJ-2GE0R00X; Num Pins: 2; Part Class: RESISTORS; Price: 0; RoHS Compliant: Yes; Tolerance: 5%
SW3 SW4 = SPST4: SWITCHES - 4 POS, 8 PIN, Ultra-mini SMT Half-pitch Slider DIP Switch; AGILE_LINK: http://sj-agile9app/Agile/PLMServlet?action=OpenEmailObject&classid=10000&objid=258073635; Item Num: K15518-001; LIFECYCLE_PHASE: Preliminary; Lead Free Status: Not Lead Free; MFR_LIFECYCLE: Active; Manufacturer: Wurth Electronik; Manufacturer Part Num: 416131160804; Num Pins: 8; PART_SUBCLASS: SWITCHES; RoHS Compliant: RoHS Compliant
U23 = Si52204: IC,CLK_GEN,32,QFN,N/A,GNRTR,PLL,; Item Num: K21260-016; Manufacturer: Silicon Labs Inc.; Manufacturer Part Num: SI52204-A01BGMR
U24 U25 = Si53254A-D02AM: IC,CLK_DRVR,40QFN,N/A,BUF,NON-PLL; Item Num: N45221-001; Manufacturer: Silabs
Y2 = CRYSTAL_SM_13: CRYSTAL - MINI XTL, 25.00MHZ, FREQ +/-50PPM, RANGE +/-30PPM -20~70C, 18PF, 2.0MM X 1.6MM SMD; Item Num: K72195-001; Lead Free Status: Yes; MFR_LIFECYCLE: Active; Manufacturer: Epson Toyocom; Manufacturer Part Num: FA-128 25.0000MB-C; Num Pins: 4; RoHS Compliant: Yes
U6 = AgileX-I_2957A: Item Num: 99C7VA
R6298 = Resistor,_0402_0: RES D,0402,0.00 OHM,5.00%,1/16W; Agile Part Number: 02495; Item Num: A93549-001; Manufacturer: YAGEO CORP.; Manufacturer Part Num: ERJ-2GE0R00X; Package: 0402; Part Number: ERJ-2GE0R00X; Tolerance: ± 5%
R6309 R6312 = RESISTOR: RES,150 OHMS,1.0%,1/16W,0402; Item Num: G60609-012; Manufacturer: Yageo; Manufacturer Part Num: RC0402FR-07150RL; Num Pins: 2; Part Class: RESISTORS; TOLERANCE: +/-1%
R6310 R6311 R6313 R6314 R6322 R6323 = RESISTOR: RES ZERO OHM 1/16W 5% 0402 SMD; Agile IPN: P02-14020R; Altera Part No.: P02-14020R; Item Num: H30887-001; Lead Free Status: No; Manufacturer: Panasonic; Manufacturer Part Num: ERJ-2GE0R00X; Num Pins: 2; Part Class: RESISTORS; RoHS Compliant: Yes; Tolerance: 5%
C477-C480 C482 C486 C488 C490 = CAP: CAPC,  X7R, 0402, 0.1uF, 25V, ±20%; Item Num: K13660-001; LIFECYCLE_PHASE: Active; Lead Free Status: Lead Free; Manufacturer: Murata; Manufacturer Part Num: GRM155R71E104KE14D; Num Pins: 2; Part Class: CAPACITORS; Price: 0; RoHS Compliant: RoHS Compliant
C481 C484 C485 C489 = CAP: CAPC,  X7R, 0402, 0.1uF, 25V, ±20%; Dielectric: Y5V; Item Num: K13660-001; LIFECYCLE_PHASE: Active; Lead Free Status: Lead Free; MFR_LIFECYCLE: Active; Manufacturer: Murata; Manufacturer Part Num: GRM155R71E104KE14D; Num Pins: 2; PART_SUBCLASS: CAPACITORS; Part Class: CAPACITORS; RATED_VOLTAGE: 25V; RoHS Compliant: RoHS Compliant; Tolerance: +80%/-20%
C483 C487 = CAP: CAPC,  X7R, 0402, 0.1uF, 25V, ±20%; Dielectric: X7R; Item Num: K13660-001; LIFECYCLE_PHASE: Active; Lead Free Status: Lead Free; MFR_LIFECYCLE: Active; Manufacturer: Murata; Manufacturer Part Num: GRM155R71E104KE14D; Num Pins: 2; PART_SUBCLASS: CAPACITORS; Part Class: CAPACITORS; RATED_VOLTAGE: 25V; RoHS Compliant: RoHS Compliant; Tolerance: +80%/-20%
R309 R310 = RESISTOR: RES ZERO OHM 1/16W 5% 0402 SMD; Altera Part No.: P02-14020R; Item Num: H30887-001; Lead Free Status: No; Manufacturer: Panasonic; Manufacturer Part Num: ERJ-2GE0R00X; Num Pins: 2; Part Class: RESISTORS; Price: 0; RoHS Compliant: Yes; Tolerance: 5%
U26 U27 = FXMA2102UMX: Dual Supply, 2-Bit Voltage Translator/Buffer/Repeater/Isolator for I2C application; Item Num: E87189-001; Manufacturer: Fairchild
U28-U32 = MAX3378E_0: IC - QUAD LOW-VOLTAGE LEVEL TRANSLATOR, +/- 15KV, ESD-PROTECTED, 1UA, 16MBPS; Item Num: C34337-001; Manufacturer: Maxim; Manufacturer Part Num: MAX3378EEUD
C494 = CAP: CAP CER 1000PF 1000V X7R 1206; AGILE_LINK: http://sj-agile9app/Agile/PLMServlet?action=OpenEmailObject&classid=10000&objid=215384813; CAPACITANCE: 1000pF; LIFECYCLE_PHASE: Active; Lead Free Status: Lead Free; MFR_LIFECYCLE: Active; Manufacturer: Murata; Manufacturer Part Num: GRM31BR73A102KW01L; Num Pins: 2; PACKAGING: Tape & Reel (TR); PART_SUBCLASS: CAPACITORS; RATED_VOLTAGE: 1000V; RoHS Compliant: RoHS Compliant; Supplier Part Num: GRM31BR73A102KW01L; Tolerance: +/-10%
D1 D3 = LED_WURTH: LED GREEN CLEAR 0603 SMD; Item Num: J48659-001; Manufacturer: Kingbright; Manufacturer Part Num: APT1608CGCK; Num Pins: 2
D2 D4 = APHB1608CGKSYKC: LED,1608,SM,GRN/YEL,V,1.00,RC,2,; Item Num: G93404-001; Manufacturer: Kingbright
HW1 = LIGHTPIPE_P-U90-1101-T00A-BP_2: QUAD STACKED,LIGHTPIPE - RIGHT ANGLE; IPN: N/A; Item Num: K33020-001; Manufacturer: Amphenol; Manufacturer Part Num: P-U90-1101-T00A-BP
MTH1 MTH2 MTH4 MTH5 = MNT_HOLE_1
Q1-Q6 = PWRMOSFET_EN_GSD_0: IC, MOSFET, N-Channel, 20V; Item Num: K21465-001; Manufacturer: Fairchild; Manufacturer Part Num: FDV305N_NL
R338 R342 R343 R350 R354 R355 = RESISTOR: RES 200 OHM 1/16W 5% 0402 SMD; Item Num: K15618-001; Manufacturer: Panasonic; Manufacturer Part Num: ERJ-2GEJ201X; Num Pins: 2; Part Class: RESISTORS; RoHS Compliant: Yes
R371 = RESISTOR: RES,1M OHMS,5.0%,1/16W,0402; AGILE_LINK: http://sj-agile9app/Agile/PLMServlet?action=OpenEmailObject&classid=10000&objid=146548997; Item Num: K15866-001; LIFECYCLE_PHASE: Active; Lead Free Status: No; MFR_LIFECYCLE: Active; Manufacturer: Panasonic; Manufacturer Part Num: ERJ-2GEJ105X; Num Pins: 2; PART_SUBCLASS: RESISTORS; POWER: 1/16W; RESISTANCE: 1M; RoHS Compliant: Yes; TOLERANCE: +/-5%

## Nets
GND: C425.2 C426.2 C427.2 C428.2 C429.2 C430.2 C431.2 C432.2 C433.2 C434.2 C435.2 C436.2 C437.2 C438.2 C439.2 C440.2 C441.2 C442.2 C443.2 C444.2 C455.2 C456.2 C457.2 C458.2 C459.2 C460.2 C461.2 C462.2 C463.2 C464.2 C471.2 C472.2 C477.1 C478.1 C479.1 C480.1 C481.2 C482.1 C483.2 C484.2 C485.2 C486.1 C487.2 C488.1 C489.2 C490.1 C494.2 C1293.2 C1294.2 C1389.2 C1390.2 C1391.2 C1392.2 C1393.1 C1394.1 C1395.2 C1396.2 C1397.2 C1398.2 C1399.1 C1400.1 Q1.2(SOURCE) Q2.2(SOURCE) Q3.2(SOURCE) Q4.2(SOURCE) Q5.2(SOURCE) Q6.2(SOURCE) R223.2 R225.2 R242.2 R244.2 R246.2 R248.2 R253.2 R260.2 R264.2 R267.2 R270.2 R272.2 R284.1 R285.1 R286.1 R288.1 R294.2 R304.2 R317.1 R318.1 R319.1 R320.1 R344.2 R345.2 R346.2 R351.2 R352.2 R353.2 R371.1 R995.2 R6298.1 R6310.2 R6311.2 R6313.2 R6314.2 R6322.2 R6323.2 U6.A69(GND) U6.A72(GND) U6.A74(GND) U6.A76(GND) U6.A78(GND) U6.A80(GND) U6.A82(GND) U6.AA63(GND) U6.AA65(GND) U6.AB10(GND) U6.AB22(GND) U6.AC72(GND) U6.AC74(GND) U6.AC78(GND) U6.AC80(GND) U6.AD64(GND) U6.AE8(GND) U6.AE12(GND) U6.AE20(GND) U6.AE24(GND) U6.AF75(GND) U6.AF77(GND) U6.AF81(GND) U6.AF83(GND) U6.AG27(GND) U6.AG29(GND) U6.AG31(GND) U6.AG33(GND) U6.AG35(GND) U6.AG37(GND) U6.AG39(GND) U6.AG41(GND) U6.AG43(GND) U6.AG45(GND) U6.AG47(GND) U6.AG49(GND) U6.AG51(GND) U6.AG53(GND) U6.AG55(GND) U6.AG57(GND) U6.AG59(GND) U6.AG61(GND) U6.AH1(GND) U6.AH6(GND) U6.AH14(GND) U6.AH18(GND) U6.AJ72(GND) U6.AJ76(GND) U6.AJ78(GND) U6.AJ82(GND) U6.AK26(GND) U6.AL3(GND) U6.AL12(GND) U6.AL16(GND) U6.AL24(GND) U6.AM73(GND) U6.AM75(GND) U6.AM79(GND) U6.AM81(GND) U6.AN63(GND) U6.AN65(GND) U6.AN68(GND) U6.AP6(GND) U6.AP10(GND) U6.AP18(GND) U6.AP22(GND) U6.AR72(GND) U6.AR74(GND) U6.AR78(GND) U6.AR80(GND) U6.AU8(GND) U6.AU12(GND) U6.AU20(GND) U6.AU24(GND) U6.AW75(GND) U6.AW77(GND) U6.AW81(GND) U6.AW83(GND) U6.AY26(GND) U6.AY28(GND) U6.AY30(GND) U6.AY32(GND) U6.AY34(GND) U6.AY36(GND) U6.AY38(GND) U6.AY40(GND) U6.AY42(GND) U6.AY44(GND) U6.AY46(GND) U6.AY48(GND) U6.AY50(GND) U6.AY52(GND) U6.AY54(GND) U6.AY56(GND) U6.AY58(GND) U6.AY60(GND) U6.AY62(GND) U6.B5(GND) U6.B9(GND) U6.B65(GND) U6.BA1(GND) U6.BA6(GND) U6.BA14(GND) U6.BA18(GND) U6.BB72(GND) U6.BB76(GND) U6.BB78(GND) U6.BB82(GND) U6.BD3(GND) U6.BD12(GND) U6.BD16(GND) U6.BD24(GND) U6.BE73(GND) U6.BE75(GND) U6.BE79(GND) U6.BE81(GND) U6.BF64(GND) U6.BF66(GND) U6.BF70(GND) U6.BG6(GND) U6.BG10(GND) U6.BG18(GND) U6.BG22(GND) U6.BH72(GND) U6.BH74(GND) U6.BH78(GND) U6.BH80(GND) U6.BJ35(GND) U6.BJ37(GND) U6.BJ39(GND) U6.BJ41(GND) U6.BJ43(GND) U6.BJ45(GND) U6.BJ47(GND) U6.BJ49(GND) U6.BJ51(GND) U6.BJ53(GND) U6.BJ55(GND) U6.BK8(GND) U6.BK12(GND) U6.BK20(GND) U6.BK24(GND) U6.BL75(GND) U6.BL77(GND) U6.BL81(GND) U6.BL83(GND) U6.BM36(GND) U6.BM56(GND) U6.BN1(GND) U6.BN6(GND) U6.BN14(GND) U6.BN18(GND) U6.BP72(GND) U6.BP76(GND) U6.BP78(GND) U6.BP82(GND) U6.BR27(GND) U6.BR29(GND) U6.BR31(GND) U6.BR33(GND) U6.BR35(GND) U6.BR37(GND) U6.BR57(GND) U6.BR59(GND) U6.BR61(GND) U6.BT3(GND) U6.BT12(GND) U6.BT16(GND) U6.BT24(GND) U6.BU73(GND) U6.BU75(GND) U6.BU79(GND) U6.BU81(GND) U6.BV40(GND) U6.BV42(GND) U6.BV44(GND) U6.BV46(GND) U6.BV48(GND) U6.BV50(GND) U6.BV52(GND) U6.BV54(GND) U6.BV56(GND) U6.BW6(GND) U6.BW10(GND) U6.BW18(GND) U6.BW22(GND) U6.BY72(GND) U6.BY74(GND) U6.BY78(GND) U6.BY80(GND) U6.C67(GND) U6.C73(GND) U6.C75(GND) U6.C79(GND) U6.C81(GND) U6.C83(GND) U6.CA63(GND) U6.CA65(GND) U6.CA68(GND) U6.CB8(GND) U6.CB12(GND) U6.CB20(GND) U6.CB24(GND) U6.CC75(GND) U6.CC77(GND) U6.CC81(GND) U6.CC83(GND) U6.CD36(GND) U6.CD38(GND) U6.CD40(GND) U6.CD42(GND) U6.CD44(GND) U6.CD46(GND) U6.CD48(GND) U6.CD50(GND) U6.CD52(GND) U6.CD54(GND) U6.CD62(GND) U6.CD64(GND) U6.CD66(GND) U6.CE1(GND) U6.CE6(GND) U6.CE14(GND) U6.CE18(GND) U6.CF72(GND) U6.CF76(GND) U6.CF78(GND) U6.CF82(GND) U6.CG61(GND) U6.CH3(GND) U6.CH12(GND) U6.CH16(GND) U6.CH24(GND) U6.CJ73(GND) U6.CJ75(GND) U6.CJ79(GND) U6.CJ81(GND) U6.CK26(GND) U6.CK28(GND) U6.CK30(GND) U6.CK32(GND) U6.CK34(GND) U6.CK36(GND) U6.CK38(GND) U6.CK40(GND) U6.CK42(GND) U6.CK44(GND) U6.CK46(GND) U6.CK48(GND) U6.CK50(GND) U6.CK52(GND) U6.CK54(GND) U6.CK58(GND) U6.CK60(GND) U6.CK62(GND) U6.CK66(GND) U6.CL6(GND) U6.CL10(GND) U6.CL18(GND) U6.CL22(GND) U6.CM72(GND) U6.CM74(GND) U6.CM78(GND) U6.CM80(GND) U6.CN59(GND) U6.CN63(GND) U6.CP8(GND) U6.CP12(GND) U6.CP20(GND) U6.CP24(GND) U6.CR38(GND) U6.CR52(GND) U6.CR56(GND) U6.CR58(GND) U6.CR62(GND) U6.CR66(GND) U6.CT75(GND) U6.CT77(GND) U6.CT81(GND) U6.CT83(GND) U6.CU29(GND) U6.CU45(GND) U6.CU51(GND) U6.CU57(GND) U6.CV1(GND) U6.CV6(GND) U6.CV14(GND) U6.CV18(GND) U6.CW72(GND) U6.CW76(GND) U6.CW78(GND) U6.CW82(GND) U6.CY40(GND) U6.CY46(GND) U6.CY52(GND) U6.CY64(GND) U6.CY66(GND) U6.D4(GND) U6.DA3(GND) U6.DA12(GND) U6.DA16(GND) U6.DA24(GND) U6.DB73(GND) U6.DB75(GND) U6.DB79(GND) U6.DB81(GND) U6.DC33(GND) U6.DC37(GND) U6.DC41(GND) U6.DC47(GND) U6.DC53(GND) U6.DC59(GND) U6.DC61(GND) U6.DC63(GND) U6.DD6(GND) U6.DD10(GND) U6.DD18(GND) U6.DD22(GND) U6.DE72(GND) U6.DE74(GND) U6.DE78(GND) U6.DE80(GND) U6.DF30(GND) U6.DF34(GND) U6.DF42(GND) U6.DF48(GND) U6.DF54(GND) U6.DF58(GND) U6.DF60(GND) U6.DF66(GND) U6.DG8(GND) U6.DG12(GND) U6.DG20(GND) U6.DG24(GND) U6.DH75(GND) U6.DH77(GND) U6.DH79(GND) U6.DH81(GND) U6.DH83(GND) U6.DJ29(GND) U6.DJ35(GND) U6.DJ37(GND) U6.DJ43(GND) U6.DJ49(GND) U6.DJ55(GND) U6.DK1(GND) U6.DK6(GND) U6.DK14(GND) U6.DK18(GND) U6.DL72(GND) U6.DL76(GND) U6.DL80(GND) U6.DL82(GND) U6.DM28(GND) U6.DM36(GND) U6.DM38(GND) U6.DM44(GND) U6.DM50(GND) U6.DM56(GND) U6.DM62(GND) U6.DM66(GND) U6.DN3(GND) U6.DN12(GND) U6.DN16(GND) U6.DN24(GND) U6.DP73(GND) U6.DP75(GND) U6.DP77(GND) U6.DP81(GND) U6.DP83(GND) U6.DR31(GND) U6.DR35(GND) U6.DR39(GND) U6.DR57(GND) U6.DT6(GND) U6.DT10(GND) U6.DT18(GND) U6.DT22(GND) U6.DU72(GND) U6.DU74(GND) U6.DU76(GND) U6.DU78(GND) U6.DU80(GND) U6.DV28(GND) U6.DV32(GND) U6.DV58(GND) U6.DV62(GND) U6.DV66(GND) U6.DW8(GND) U6.DW12(GND) U6.DW20(GND) U6.DW24(GND) U6.DY75(GND) U6.DY77(GND) U6.DY79(GND) U6.DY83(GND) U6.E72(GND) U6.E74(GND) U6.E78(GND) U6.E80(GND) U6.E82(GND) U6.EA59(GND) U6.EA63(GND) U6.EB1(GND) U6.EB6(GND) U6.EB14(GND) U6.EB18(GND) U6.EC72(GND) U6.EC80(GND) U6.EC82(GND) U6.ED28(GND) U6.ED32(GND) U6.ED36(GND) U6.ED54(GND) U6.ED66(GND) U6.EE3(GND) U6.EE12(GND) U6.EE16(GND) U6.EE24(GND) U6.EF75(GND) U6.EF77(GND) U6.EF81(GND) U6.EF83(GND) U6.EG37(GND) U6.EG55(GND) U6.EG59(GND) U6.EG65(GND) U6.EH6(GND) U6.EH10(GND) U6.EH18(GND) U6.EH22(GND) U6.EJ28(GND) U6.EJ34(GND) U6.EJ38(GND) U6.EJ56(GND) U6.EJ58(GND) U6.EJ60(GND) U6.EJ64(GND) U6.EJ66(GND) U6.EJ70(GND) U6.EK78(GND) U6.EK80(GND) U6.EL31(GND) U6.EL33(GND) U6.EL35(GND) U6.EL39(GND) U6.EL57(GND) U6.EL59(GND) U6.EL61(GND) U6.EL63(GND) U6.EL65(GND) U6.EL68(GND) U6.EM8(GND) U6.EM12(GND) U6.EM20(GND) U6.EM24(GND) U6.EN75(GND) U6.EN77(GND) U6.EN79(GND) U6.EN83(GND) U6.EP28(GND) U6.EP30(GND) U6.EP36(GND) U6.EP62(GND) U6.ER1(GND) U6.ER6(GND) U6.ER14(GND) U6.ER18(GND) U6.ET72(GND) U6.ET74(GND) U6.ET76(GND) U6.ET80(GND) U6.ET82(GND) U6.EU68(GND) U6.EV3(GND) U6.EV12(GND) U6.EV16(GND) U6.EV24(GND) U6.EW73(GND) U6.EW77(GND) U6.EW81(GND) U6.EW83(GND) U6.EY28(GND) U6.EY32(GND) U6.EY54(GND) U6.EY58(GND) U6.EY60(GND) U6.EY70(GND) U6.F2(GND) U6.F5(GND) U6.F9(GND) U6.F13(GND) U6.F17(GND) U6.F21(GND) U6.F25(GND) U6.F27(GND) U6.F29(GND) U6.F31(GND) U6.F33(GND) U6.F35(GND) U6.F37(GND) U6.F39(GND) U6.F41(GND) U6.F43(GND) U6.F45(GND) U6.F47(GND) U6.F49(GND) U6.F51(GND) U6.F53(GND) U6.F55(GND) U6.F57(GND) U6.F59(GND) U6.F61(GND) U6.F63(GND) U6.F65(GND) U6.FA6(GND) U6.FA10(GND) U6.FA18(GND) U6.FA22(GND) U6.FB72(GND) U6.FB74(GND) U6.FB78(GND) U6.FB80(GND) U6.FC31(GND) U6.FC35(GND) U6.FC37(GND) U6.FC55(GND) U6.FC63(GND) U6.FC65(GND) U6.FC68(GND) U6.FD8(GND) U6.FD12(GND) U6.FD20(GND) U6.FD24(GND) U6.FE75(GND) U6.FE77(GND) U6.FE79(GND) U6.FE83(GND) U6.FF28(GND) U6.FF32(GND) U6.FF34(GND) U6.FF36(GND) U6.FF38(GND) U6.FF56(GND) U6.FF62(GND) U6.FF70(GND) U6.FG1(GND) U6.FG6(GND) U6.FG14(GND) U6.FG18(GND) U6.FH72(GND) U6.FH74(GND) U6.FH76(GND) U6.FH80(GND) U6.FH82(GND) U6.FJ33(GND) U6.FJ35(GND) U6.FJ63(GND) U6.FJ65(GND) U6.FJ68(GND) U6.FK3(GND) U6.FK12(GND) U6.FK16(GND) U6.FK24(GND) U6.FL75(GND) U6.FL77(GND) U6.FL81(GND) U6.FL83(GND) U6.FM28(GND) U6.FM30(GND) U6.FM34(GND) U6.FM60(GND) U6.FN6(GND) U6.FN10(GND) U6.FN18(GND) U6.FN22(GND) U6.FP76(GND) U6.FP78(GND) U6.FP80(GND) U6.FR29(GND) U6.FR35(GND) U6.FR57(GND) U6.FR59(GND) U6.FR65(GND) U6.FR68(GND) U6.FT8(GND) U6.FT12(GND) U6.FT20(GND) U6.FT24(GND) U6.FU75(GND) U6.FU77(GND) U6.FU79(GND) U6.FU83(GND) U6.FV28(GND) U6.FV36(GND) U6.FV54(GND) U6.FV60(GND) U6.FV62(GND) U6.FV64(GND) U6.FW1(GND) U6.FW6(GND) U6.FW14(GND) U6.FW18(GND) U6.FY74(GND) U6.FY76(GND) U6.FY78(GND) U6.FY80(GND) U6.FY82(GND) U6.G67(GND) U6.G71(GND) U6.G75(GND) U6.G77(GND) U6.G81(GND) U6.G83(GND) U6.GA31(GND) U6.GA35(GND) U6.GA37(GND) U6.GA55(GND) U6.GA61(GND) U6.GA68(GND) U6.GB3(GND) U6.GB12(GND) U6.GB16(GND) U6.GB24(GND) U6.GC73(GND) U6.GC75(GND) U6.GC77(GND) U6.GC79(GND) U6.GC81(GND) U6.GC83(GND) U6.GD28(GND) U6.GD32(GND) U6.GD38(GND) U6.GD56(GND) U6.GD70(GND) U6.GE6(GND) U6.GE10(GND) U6.GE18(GND) U6.GE22(GND) U6.GF39(GND) U6.GF57(GND) U6.GF61(GND) U6.GF63(GND) U6.GF68(GND) U6.GG72(GND) U6.GG74(GND) U6.GG76(GND) U6.GG80(GND) U6.GG82(GND) U6.GH28(GND) U6.GH32(GND) U6.GH36(GND) U6.GH58(GND) U6.GH62(GND) U6.GH64(GND) U6.GH70(GND) U6.GJ8(GND) U6.GJ12(GND) U6.GJ20(GND) U6.GJ24(GND) U6.GK73(GND) U6.GK75(GND) U6.GK79(GND) U6.GK81(GND) U6.GL61(GND) U6.GL65(GND) U6.GL68(GND) U6.GM1(GND) U6.GM6(GND) U6.GM14(GND) U6.GM18(GND) U6.GN72(GND) U6.GN74(GND) U6.GN76(GND) U6.GN78(GND) U6.GN80(GND) U6.GP28(GND) U6.GP34(GND) U6.GP54(GND) U6.GR3(GND) U6.GR12(GND) U6.GR16(GND) U6.GR24(GND) U6.GT73(GND) U6.GT75(GND) U6.GT77(GND) U6.GT81(GND) U6.GT83(GND) U6.GU31(GND) U6.GU33(GND) U6.GU35(GND) U6.GU37(GND) U6.GU55(GND) U6.GU57(GND) U6.GU59(GND) U6.GU61(GND) U6.GU68(GND) U22.65(ePAD) U23.8(VSSR) U23.32(GNDA) U23.33(GND_PAD) U24.11(GND1) U24.12(GND2) U24.41(GND_PAD) U25.11(GND1) U25.12(GND2) U25.41(GND_PAD) U26.4(GND) U27.4(GND) U28.7(GND) U29.7(GND) U30.7(GND) U31.7(GND) U32.7(GND) Y2.2 Y2.4 ; also on sheet 9 10 11 13 14 15 16 17 18 19 20 21 22 23 25 26 27 28 29 30 31 32 33 34 35 36 38 39 40 48 49 50 51 52 53 54 55 56 57 58 59 60 61 62 63 64 65 66 67 68 69 70 71 72 73 74 75 76 77
1p2V_DDR4_CH01: C481.1 C485.1 C487.1 C489.1 R321.1 R322.2 R323.2 R332.2 R335.2 R336.2 R337.1 U28.1(VL) U30.1(VL) U31.1(VL) U31.8(TSn) U32.1(VL) U32.8(TSn) ; also on sheet 9 10 11 14 15 16 32 39 52 70 72 76 77
1p8V_SI52204: C456.1 C457.1 C458.1 C459.1 C460.1 C461.1 C462.1 C463.1 FB9.1 U23.5(VDDX) U23.6(VDDR) U23.15(VDD_IO0) U23.19(VDD0) U23.24(VDD_IO1) U23.29(VDD1) U23.31(VDDA)
2p5V: C483.1 FB6.2 FB13.2 R291.2 R292.2 R293.2 R303.2 R329.2 R330.2 R994.2 U29.1(VL) U29.8(TSn) ; also on sheet 9 10 11 14 15 16 19 20 73
2p5V_SI53254_2: C471.1 C472.1 C1395.1 C1396.1 C1397.1 C1398.1 FB13.1 U25.1(VDD_DIG) U25.4(VDD) U25.9(VDDA) U25.15(VDDO0) U25.18(VDDO1) U25.25(VDDO2)
3p3V_STBY: R287.1 ; also on sheet 30 48 49 50 51 52 53 57 77
BUF1_CLK0_N: C466.2 R986.1 U24.3(CLK_IN1b)
BUF1_CLK0_P: C465.2 R985.1 U24.2(CLK_IN1)
BUF1_CLK1_N: C468.2 R988.1 U24.8(CLK_IN2b)
BUF1_CLK1_P: C467.2 R987.1 U24.7(CLK_IN2)
BUF1_Q0_N: R929.2 U24.13(OUT0b)
BUF1_Q0_P: R928.2 U24.14(OUT0)
BUF1_Q1_N: R931.2 U24.16(OUT1b)
BUF1_Q1_P: R930.2 U24.17(OUT1)
BUF1_Q3_N: R6321.1 U24.23(OUT3b)
BUF1_Q3_P: R6320.1 U24.24(OUT3)
BUF2_CLK0_N: C474.2 R996.1 U25.3(CLK_IN1b)
BUF2_CLK0_P: C473.2 R993.1 U25.2(CLK_IN1)
BUF2_CLK1_N: C476.2 R998.1 U25.8(CLK_IN2b)
BUF2_CLK1_P: C475.2 R997.1 U25.7(CLK_IN2)
BUF2_Q0_N: R933.2 U25.13(OUT0b)
BUF2_Q0_P: R932.2 U25.14(OUT0)
BUF2_Q1_N: R935.2 U25.16(OUT1b)
BUF2_Q1_P: R934.2 U25.17(OUT1)
BUF2_Q2_N: R6318.1 U25.21(OUT2b)
BUF2_Q2_P: R6317.1 U25.22(OUT2)
BUFF1_IMP_SEL: R267.1 R268.1 U24.19(IMP_SEL)
BUFF1_OE0N: R269.1 R270.1 U24.31(OEb_OUT0)
BUFF1_OE1N: R271.1 R272.1 U24.32(OEb_OUT1)
BUFF1_OE2N: R983.1 U24.36(OEb_OUT2)
BUFF1_OE3N: R984.1 U24.37(OEb_OUT3)
BUFF2_IMP_SEL: R994.1 R995.1 U25.19(IMP_SEL)
BUFF2_OE0N: R293.1 R294.1 U25.31(OEb_OUT0)
BUFF2_OE1N: R303.1 R304.1 U25.32(OEb_OUT1)
BUFF2_OE2N: R291.1 U25.36(OEb_OUT2)
BUFF2_OE3N: R292.1 U25.37(OEb_OUT3)
CLK_CXL_CONN_N: C474.1 ; also on sheet 32
CLK_CXL_CONN_P: C473.1 ; also on sheet 32
CLK_DDR4_CH0_N: R230.1 ; also on sheet 23
CLK_DDR4_CH0_P: R229.1 ; also on sheet 23
CLK_DDR4_CH1_N: R1064.1 ; also on sheet 21
CLK_DDR4_CH1_P: R1063.1 ; also on sheet 21
CLK_DDR4_CH2_N: R232.1 ; also on sheet 18
CLK_DDR4_CH2_P: R231.1 ; also on sheet 18
CLK_DDR4_CH3_N: R1066.1 ; also on sheet 13
CLK_DDR4_CH3_P: R1065.1 ; also on sheet 13
CLK_SYS_100M_N: R236.1 ; also on sheet 22
CLK_SYS_100M_P: R235.1 ; also on sheet 22
CORE_PMBUS_SCL: R308.1 R309.2 R313.2 U26.2(A0) ; also on sheet 54
CORE_PMBUS_SDA: R306.1 R310.2 R314.2 U26.3(A1) ; also on sheet 54
DDR4_DIMM_SCL: R330.1 U29.2(IOVL1) ; also on sheet 19 20
DDR4_DIMM_SDA: R329.1 U29.3(IOVL2) ; also on sheet 19 20
FM41_14C_PCIE_PERSTN: R6298.2 U6.EP70(GND) ; also on sheet 31
FPGA_I2C1_SCL: R323.1 U28.2(IOVL1) ; also on sheet 12
FPGA_I2C1_SDA: R322.1 U28.3(IOVL2) ; also on sheet 12
FPGA_I2C2_EN: R857.1 ; also on sheet 22
FPGA_I2C2_EN_R: R337.2 R857.2 SW4.2(A2) U30.8(TSn)
FPGA_I2C2_SCL: R336.1 U30.2(IOVL1) ; also on sheet 22
FPGA_I2C2_SDA: R335.1 U30.3(IOVL2) ; also on sheet 22
FPGA_I2C_EN: R326.1 ; also on sheet 22
FPGA_I2C_EN_R: R321.2 R326.2 SW4.1(A1) U28.8(TSn)
FPGA_OSC_CLK_1: R239.1 ; also on sheet 35
FPGA_PMBUS_EN: R316.2 SW4.4(A4) U26.5(OE) ; also on sheet 50
FPGA_SDM_SCL: R307.1 U26.7(B0) ; also on sheet 35
FPGA_SDM_SDA: R305.1 U26.6(B1) ; also on sheet 35
HPS_OSC_CLK: R237.1 ; also on sheet 36
I2C2_SCL: R333.2 R859.2 ; also on sheet 27 32 48 50 52
I2C2_SDA: R331.2 R858.2 ; also on sheet 27 32 48 50 52
I2C3_SCL: R328.1 U29.13(IOVCC1) ; also on sheet 50
I2C3_SDA: R327.1 U29.12(IOVCC2) ; also on sheet 50
IO_1p8V: C477.2 FB5.1 FB8.2 FB9.2 FB10.2 R241.2 R243.2 R245.2 R247.2 R251.2 R257.2 R263.2 R268.2 R269.2 R271.2 R282.1 R283.1 R305.2 R307.2 R983.2 R984.2 R2740.2 U26.8(VCCB) ; also on sheet 35 36 39 67 75 77
IO_1p8V_SI53254_1: C1293.1 C1294.1 C1389.1 C1390.1 C1391.1 C1392.1 FB10.1 U24.1(VDD_DIG) U24.4(VDD) U24.9(VDDA) U24.15(VDDO0) U24.18(VDDO1) U24.25(VDDO2)
IO_3p3V: C434.1 C478.2 C479.2 C480.2 C482.2 C484.1 C486.2 C488.2 C490.2 FB7.1 R224.2 R226.2 R227.2 R228.2 R281.1 R306.2 R308.2 R311.2 R312.2 R315.1 R316.1 R327.2 R328.2 R331.1 R333.1 R338.2 R339.1 R340.1 R341.1 R342.2 R343.2 R347.1 R348.1 R349.1 R350.2 R354.2 R355.2 U26.1(VCCA) U27.1(VCCA) U27.8(VCCB) U28.14(VCC) U29.14(VCC) U30.14(VCC) U31.14(VCC) U32.14(VCC) ; also on sheet 25 26 27 30 31 32 48 52 73
MAIN_I2C_SCL: R258.1 R309.1 R312.1 R324.2 U22.16(SCLK) U27.7(B0) ; also on sheet 63 77
MAIN_I2C_SDA: R261.1 R310.1 R311.1 R325.2 U22.18(SDA_SDIO) U27.6(B1) ; also on sheet 63 77
MAIN_PMBUS_EN: R315.2 SW4.3(A3) U27.5(OE) ; also on sheet 49
PCIE_CLK_LOS: R2740.1 U24.10(LOS) ; also on sheet 49
QSFPDD0_FPGA_LED0: R346.1 U31.2(IOVL1) ; also on sheet 22
QSFPDD0_FPGA_LED1: R345.1 U31.3(IOVL2) ; also on sheet 22
QSFPDD0_FPGA_LED2: R344.1 U31.4(IOVL3) ; also on sheet 22
QSFPDD0_LED0: Q1.1(GATE) R341.2 U31.13(IOVCC1)
QSFPDD0_LED1: Q3.1(GATE) R340.2 U31.12(IOVCC2)
QSFPDD0_LED2: Q2.1(GATE) R339.2 U31.11(IOVCC3)
QSFPDD1_FPGA_LED0: R353.1 U32.2(IOVL1) ; also on sheet 22
QSFPDD1_FPGA_LED1: R352.1 U32.3(IOVL2) ; also on sheet 22
QSFPDD1_FPGA_LED2: R351.1 U32.4(IOVL3) ; also on sheet 22
QSFPDD1_LED0: Q4.1(GATE) R349.2 U32.13(IOVCC1)
QSFPDD1_LED1: Q6.1(GATE) R348.2 U32.12(IOVCC2)
QSFPDD1_LED2: Q5.1(GATE) R347.2 U32.11(IOVCC3)
QSFPDD_1V2_PORT_EN: R332.1 U31.5(IOVL4) ; also on sheet 22
QSFPDD_1V2_PORT_INT_N: U32.5(IOVL4) ; also on sheet 22
QSFPDD_3V3_PORT_EN: U31.10(IOVCC4) ; also on sheet 27
QSFPDD_3V3_PORT_INT_N: U32.10(IOVCC4) ; also on sheet 27
RCOMP_FM41_BANK_14C: R6312.2 R6314.1 U6.CK70(GND)
RCOMP_FM41_BANK_15C: R6309.2 R6311.1 U6.FR27(GND)
REFCLK_CXL_15C_CH0_N: R933.1 ; also on sheet 33
REFCLK_CXL_15C_CH0_P: R932.1 ; also on sheet 33
REFCLK_CXL_15C_CH1_N: R935.1 ; also on sheet 33
REFCLK_CXL_15C_CH1_P: R934.1 ; also on sheet 33
REFCLK_CXL_EP_N: C476.1 R254.1
REFCLK_CXL_EP_P: C475.1 R252.1
REFCLK_CXL_RP_N0: R256.1 ; also on sheet 32
REFCLK_CXL_RP_N1: R262.1 ; also on sheet 32
REFCLK_CXL_RP_P0: R255.1 ; also on sheet 32
REFCLK_CXL_RP_P1: R259.1 ; also on sheet 32
REFCLK_FGT12ACH0_N: C1452.2 ; also on sheet 28
REFCLK_FGT12ACH0_P: C1451.2 ; also on sheet 28
REFCLK_FGT12ACH3_N: C454.2 ; also on sheet 28
REFCLK_FGT12ACH3_P: C453.2 ; also on sheet 28
REFCLK_FGT12ACH4_N: C446.2 ; also on sheet 28
REFCLK_FGT12ACH4_P: C445.2 ; also on sheet 28
REFCLK_FGT12ACH5_N: C448.2 ; also on sheet 28
REFCLK_FGT12ACH5_P: C447.2 ; also on sheet 28
REFCLK_FGT12ACH6_N: C452.2 ; also on sheet 28
REFCLK_FGT12ACH6_P: C451.2 ; also on sheet 28
REFCLK_FM41_14C_PCIE_N: R6321.2 R6322.1 U6.ED70(GND)
REFCLK_FM41_14C_PCIE_P: R6320.2 R6323.1 U6.EG68(GND)
REFCLK_FM41_15C_CXL_N: R6318.2 ; also on sheet 29
REFCLK_FM41_15C_CXL_P: R6317.2 ; also on sheet 40
REFCLK_PCIE_14C_CH0_N: R929.1 ; also on sheet 31
REFCLK_PCIE_14C_CH0_P: R928.1 ; also on sheet 31
REFCLK_PCIE_14C_CH1_N: R931.1 ; also on sheet 31
REFCLK_PCIE_14C_CH1_P: R930.1 ; also on sheet 31
REFCLK_PCIE_EP_EDGE_N: C466.1 ; also on sheet 30
REFCLK_PCIE_EP_EDGE_P: C465.1 ; also on sheet 30
REFCLK_PCIE_EP_N: C468.1 R250.1
REFCLK_PCIE_EP_P: C467.1 R249.1
SEL_CXL_REFCLK: R281.2 SW3.2(A2) U25.20(CLK_SEL)
SEL_PCIE_REFCLK: R282.2 SW3.3(A3) U24.20(CLK_SEL)
SI2204_OUT0n: R250.2 U23.13(DIFF_0b)
SI2204_OUT0p: R249.2 U23.12(DIFF_0)
SI2204_OUT1n: R254.2 U23.18(DIFF_1b)
SI2204_OUT1p: R252.2 U23.17(DIFF_1)
SI2204_OUT2n: R256.2 U23.22(DIFF_2b)
SI2204_OUT2p: R255.2 U23.21(DIFF_2)
SI2204_OUT3n: R262.2 U23.26(DIFF_3b)
SI2204_OUT3p: R259.2 U23.25(DIFF_3)
SI5391_1p8V_VDDO: C437.1 C438.1 C439.1 C440.1 C441.1 C442.1 C443.1 C444.1 FB8.1 U22.26(VDDO1) U22.29(VDDO2) U22.33(VDDO3) U22.40(VDDO5) U22.49(VDDO7) U22.57(VDDO9)
SI5391_2p5V_VDDO: C429.1 C430.1 C431.1 C432.1 C433.1 FB6.1 U22.22(VDDO0) U22.36(VDDO4) U22.43(VDDO6) U22.52(VDDO8)
SI5391_A0: R223.1 U22.19(A0_CSB)
SI5391_A1: R225.1 U22.17(A1_SDO)
SI5391_ENn: R288.2 SW3.1(A1) U22.11(OEB) ; also on sheet 48
SI5391_I2C_SEL: R224.1 U22.39(I2C_SEL)
SI5391_IN_SEL0: R227.1 U22.3(IN_SEL0)
SI5391_IN_SEL1: R226.1 U22.4(IN_SEL1)
SI5391_OUT0An: C448.1 U22.20(OUT0AB)
SI5391_OUT0Ap: C447.1 U22.21(OUT0A)
SI5391_OUT0n: C446.1 U22.23(OUT0B)
SI5391_OUT0p: C445.1 U22.24(OUT0)
SI5391_OUT1n: R232.2 U22.27(OUT1B)
SI5391_OUT1p: R231.2 U22.28(OUT1)
SI5391_OUT2n: R230.2 U22.30(OUT2B)
SI5391_OUT2p: R229.2 U22.31(OUT2)
SI5391_OUT3n: R1064.2 U22.34(OUT3B)
SI5391_OUT3p: R1063.2 U22.35(OUT3)
SI5391_OUT4n: C452.1 U22.37(OUT4B)
SI5391_OUT4p: C451.1 U22.38(OUT4)
SI5391_OUT5n: R1066.2 U22.41(OUT5B)
SI5391_OUT5p: R1065.2 U22.42(OUT5)
SI5391_OUT6n: C454.1 U22.44(OUT6B)
SI5391_OUT6p: C453.1 U22.45(OUT6)
SI5391_OUT7p: R239.2 U22.51(OUT7)
SI5391_OUT8n: C1452.1 U22.53(OUT8B)
SI5391_OUT8p: C1451.1 U22.54(OUT8)
SI5391_OUT9A: R237.2 U22.59(OUT9A)
SI5391_OUT9n: R236.2 U22.55(OUT9B)
SI5391_OUT9p: R235.2 U22.56(OUT9)
SI5391_RSTn: R228.1 U22.6(RSTB) ; also on sheet 48
SI5391_VDD: C425.1 C426.1 C427.1 C428.1 FB5.2 U22.32(VDD) U22.46(VDD) U22.60(VDD)
SI5391_VDDA: C435.1 C436.1 FB7.2 U22.13(VDDA)
SI5391_X1: U22.7(X1) Y1.2
SI5391_X2: U22.10(X2) Y1.4
SI5391_XA: U22.8(XA) Y1.3
SI5391_XB: U22.9(XB) Y1.1
SI52204_FS: R257.1 R260.1 U23.11(FS)
SI52204_OE0n: R241.1 R242.1 U23.14(OE_0b)
SI52204_OE1n: R245.1 R246.1 U23.16(OE_1b)
SI52204_OE2n: R247.1 R248.1 U23.23(OE_2b)
SI52204_OE3n: R243.1 R244.1 U23.27(OE_3b)
SI52204_PWRDNB: R283.2 SW3.4(A4) U23.2(PWRGD/PWRDNb)
SI52204_SA: R263.1 R264.1 U23.7(REF/SA)
SI52204_SSEN: R251.1 R253.1 U23.1(SS_EN)
N31352894: R317.2 SW4.5(B4)
N31352897: R318.2 SW4.6(B3)
N31352900: R319.2 SW4.7(B2)
N34474357: R313.1 U27.2(A0)
N34474360: R314.1 U27.3(A1)
N36270051: R324.1 U28.13(IOVCC1)
N36270054: R325.1 U28.12(IOVCC2)
N36270340: R320.2 SW4.8(B1)
N36344563: R284.2 SW3.5(B4)
N36344586: R285.2 SW3.6(B3)
N36344607: R286.2 SW3.7(B2)
N36541668: D1.A(ANODE) R338.1
N36541743: D2.3 R342.1
N36541790: D2.1 R343.1
N36541991: D3.A(ANODE) R350.1
N36542034: D4.3 R354.1
N36542055: D4.1 R355.1
N36542312: D1.C(CATHODE) Q1.3(DRAIN)
N36542538: D2.4 Q2.3(DRAIN)
N36542543: D2.2 Q3.3(DRAIN)
N36542635: D3.C(CATHODE) Q4.3(DRAIN)
N36542846: D4.4 Q5.3(DRAIN)
N36542851: D4.2 Q6.3(DRAIN)
N40287496: C455.1 U23.3(XIN/CLKIN) Y2.3
N40287524: C464.1 U23.4(XOUT) Y2.1
N40288703: R258.2 U23.10(SCLK)
N40288707: R261.2 U23.9(SDA)
N41103719: R287.2 SW3.8(B1)
N42710822: R859.1 U30.13(IOVCC1)
N42710832: R858.1 U30.12(IOVCC2)
N45280572: C1393.2 R985.2 R986.2
N45280837: C1394.2 R987.2 R988.2
N45286790: C1399.2 R993.2 R996.2
N45286851: C1400.2 R997.2 R998.2
N46986379: C494.1 MTH1.1(GND) MTH4.1(GND) R371.2
N51946602: R6309.1 R6310.1 U6.FM26(GND)
N51951812: R6312.1 R6313.1 U6.CN68(GND)

Not connected (* = marked no-connect by the designer): HW1 1(MT1)* 2(MT2)* 3(MT3)*; MTH2 1(GND)*; MTH5 1(GND)*; U22 1(IN1)* 2(IN1_N)* 5(SYNCB)* 12(INTRB)* 14(IN2)* 15(IN2_N)* 25(FDEC)* 47(LOLB)* 48(FINC)* 50(OUT7B)* 58(OUT9AB)* 61(FBIN)* 62(FBIN_N)* 63(IN0)* 64(IN0_N)*; U23 20(NC0)* 28(NC1)* 30(NC2)*; U24 5(NC1)* 6(NC2)* 21(OUT2b)* 22(OUT2)* 26(NC3)* 27(NC4)* 28(NC5)* 29(NC6)* 30(NC7)* 33(NC8)* 34(NC9)* 35(NC10)* 38(NC11)* 39(NC12)* 40(NC13)*; U25 5(NC1)* 6(NC2)* 10(LOS)* 23(OUT3b)* 24(OUT3)* 26(NC3)* 27(NC4)* 28(NC5)* 29(NC6)* 30(NC7)* 33(NC8)* 34(NC9)* 35(NC10)* 38(NC11)* 39(NC12)* 40(NC13)*; U28 4(IOVL3)* 5(IOVL4)* 6(NC0)* 9(NC1)* 10(IOVCC4)* 11(IOVCC3)*; U29 4(IOVL3)* 5(IOVL4)* 6(NC0)* 9(NC1)* 10(IOVCC4)* 11(IOVCC3)*; U30 4(IOVL3)* 5(IOVL4)* 6(NC0)* 9(NC1)* 10(IOVCC4)* 11(IOVCC3)*; U31 6(NC0)* 9(NC1)*; U32 6(NC0)* 9(NC1)*

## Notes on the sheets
sheet 41
- FPGA GND 2
sheet 42
- FPGA GND 3
sheet 43
- Clock 1
- set IO_VDD_SEL = 1,
  select VDDIO = VDDA
- 7-bit I2C Address 74h
- Default LVDS 156.25 MHz
- Default LVDS 156.25 MHz
- Default LVDS 33.33 MHz
- Default LVDS 33.33 MHz
- Default LVDS 33.33 MHz
- Default LVDS 184.32 MHz
- Default LVDS 33.33 MHz
- Default LVCMOS 100 MHz
- Default LVCMOS 125 MHz
- Default LVDS 153.6 MHz
- Default LVDS 100 MHz
- Default LVDS 25 MHz
sheet 44
- Clock 2
- CLK_SEL      Input
      0        CLKIN1
      1        CLKIN2
- OPEN = Enable
  Closed = Disable
sheet 45
- Clock 3
- CLK_SEL      Input
      0        CLKIN1
      1        CLKIN2
sheet 46
- I2C And PMBUS
- Place R288, R289 near to U20
- OPEN = Enable
  Closed = Disable
sheet 47
- QSFPDD LED
- LED 0 (Green)
- LED 1 (Green/Yellow)
- LED 2 (Green)
- LED3 (Green/Yellow)
- Port A Link
- LED2 (Green)
- Port A Act.
- LED1 (Green/Yellow)
- Port B Link
- LED0 (Green)
- Port B Act.
- Large Mounting holes on the rear of board
- Large Mounting holes on the front of board
- LED 3 (Green/Yellow)
